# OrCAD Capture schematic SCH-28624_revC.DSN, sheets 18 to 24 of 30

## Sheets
18 16 XG-T PHY 1: size B
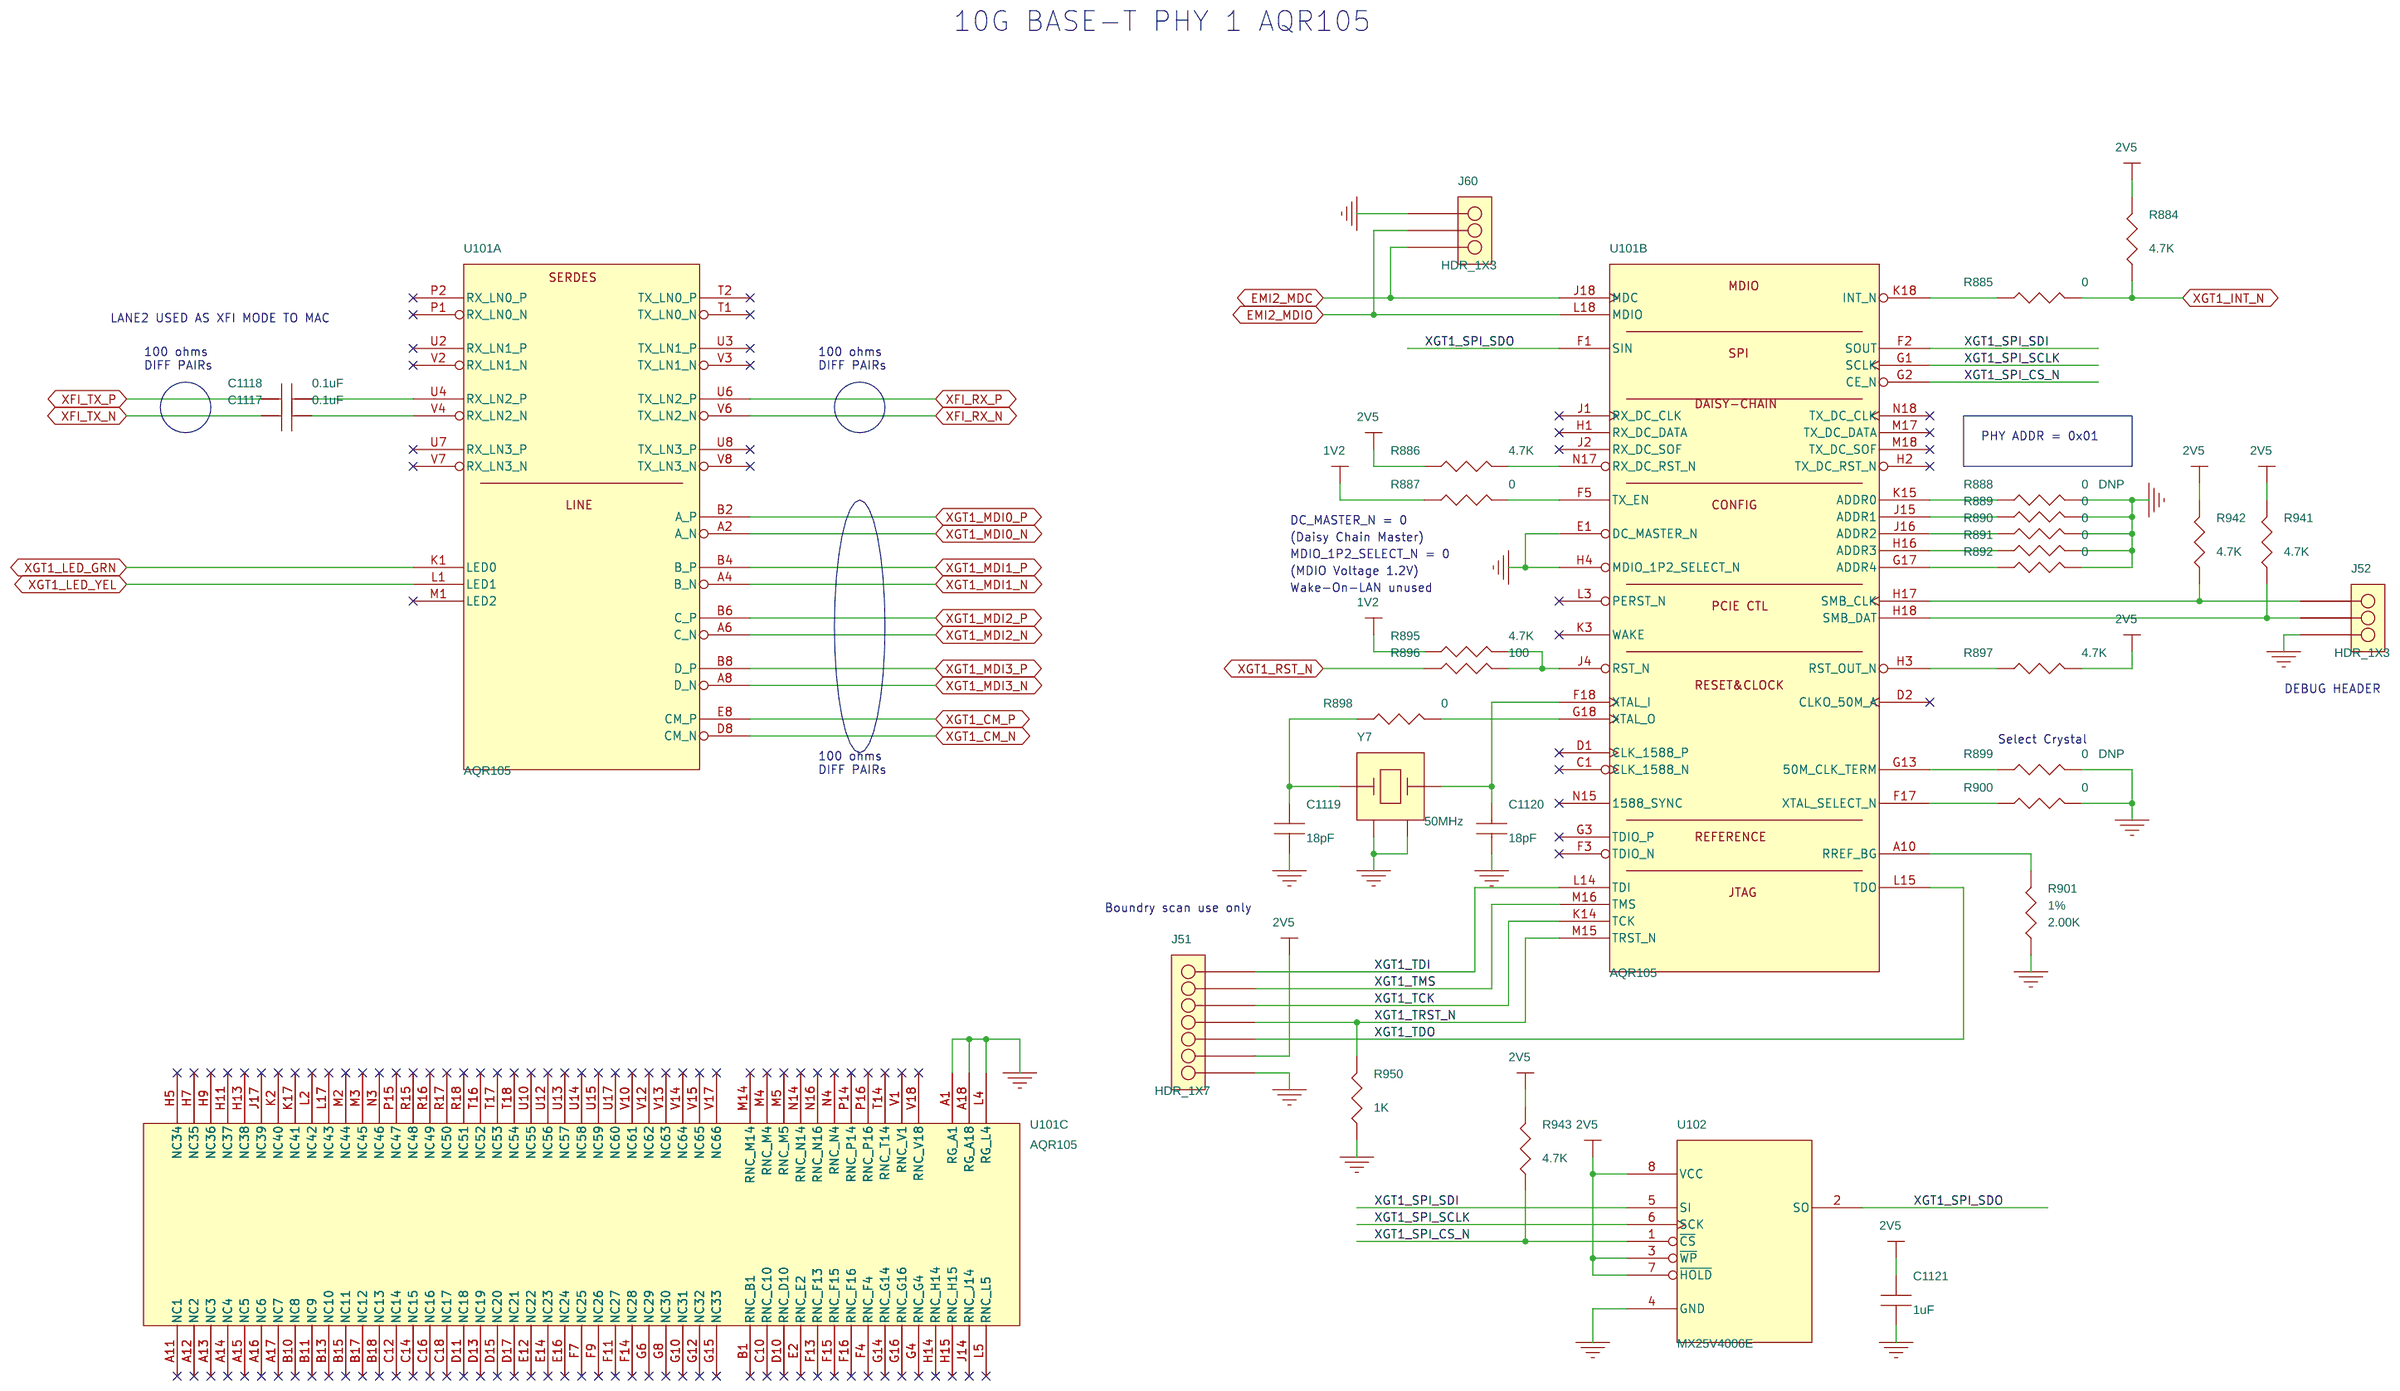
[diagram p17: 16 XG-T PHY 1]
19 17 XG-T PHY 1 Pwr: size B
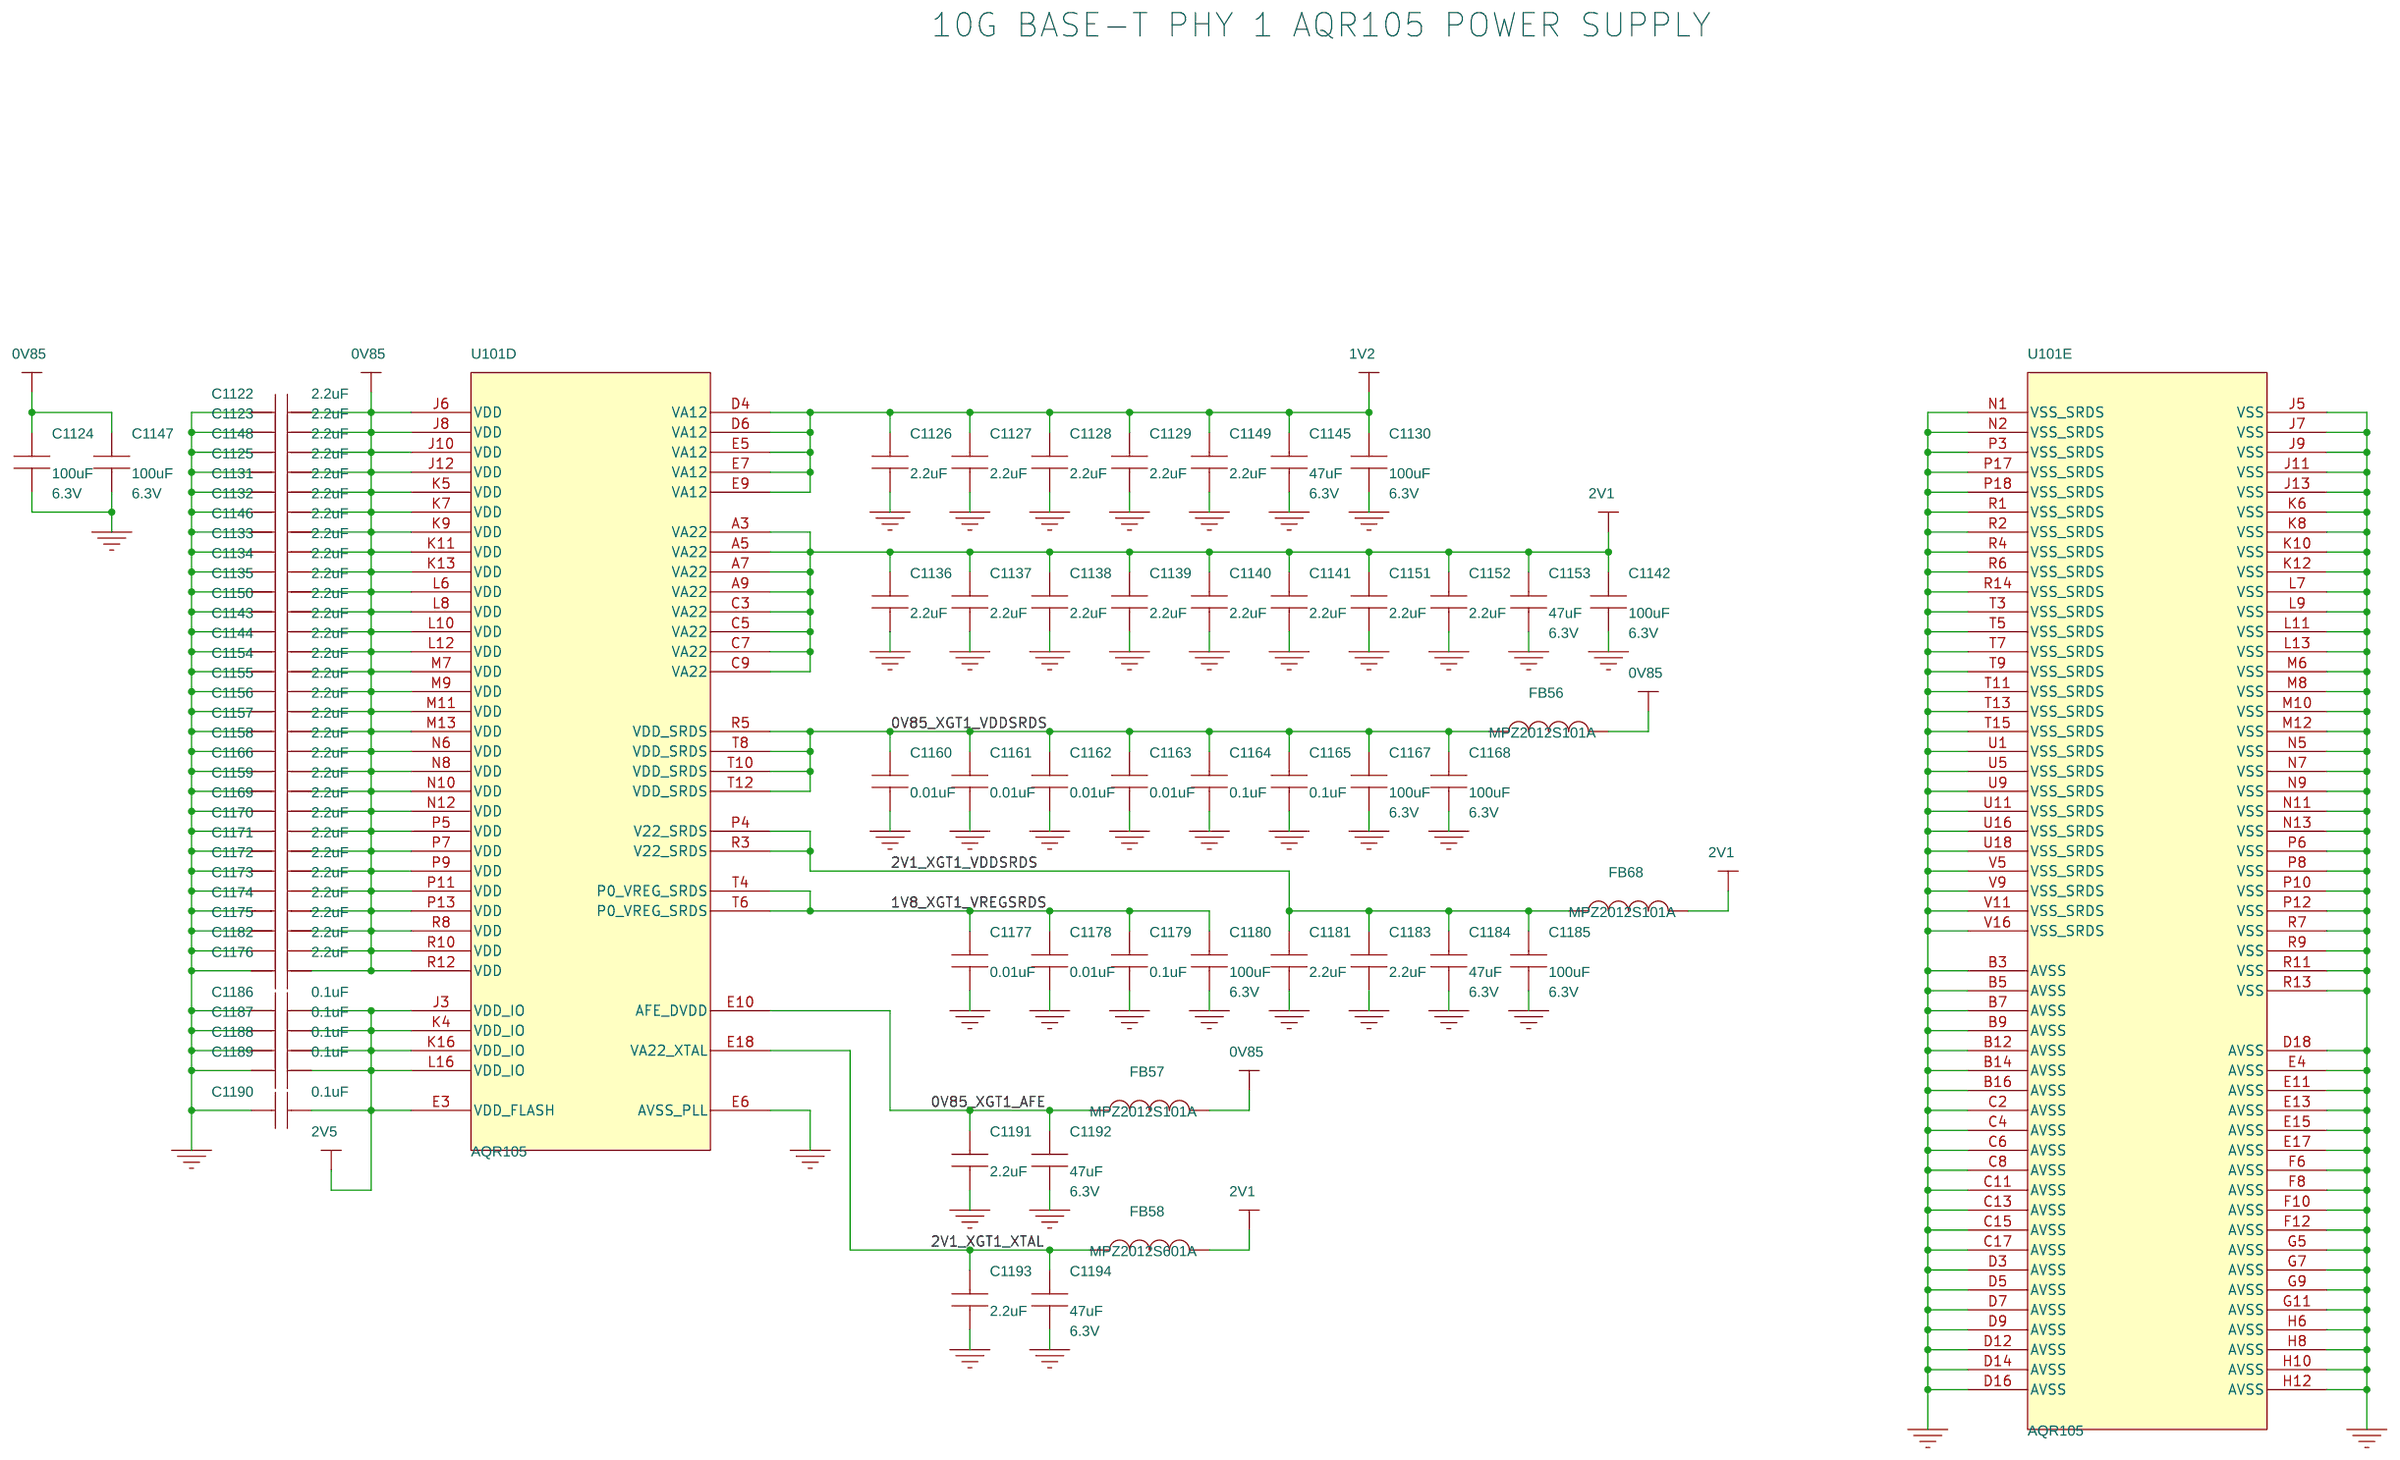
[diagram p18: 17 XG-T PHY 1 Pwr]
20 20 RJ46: size B
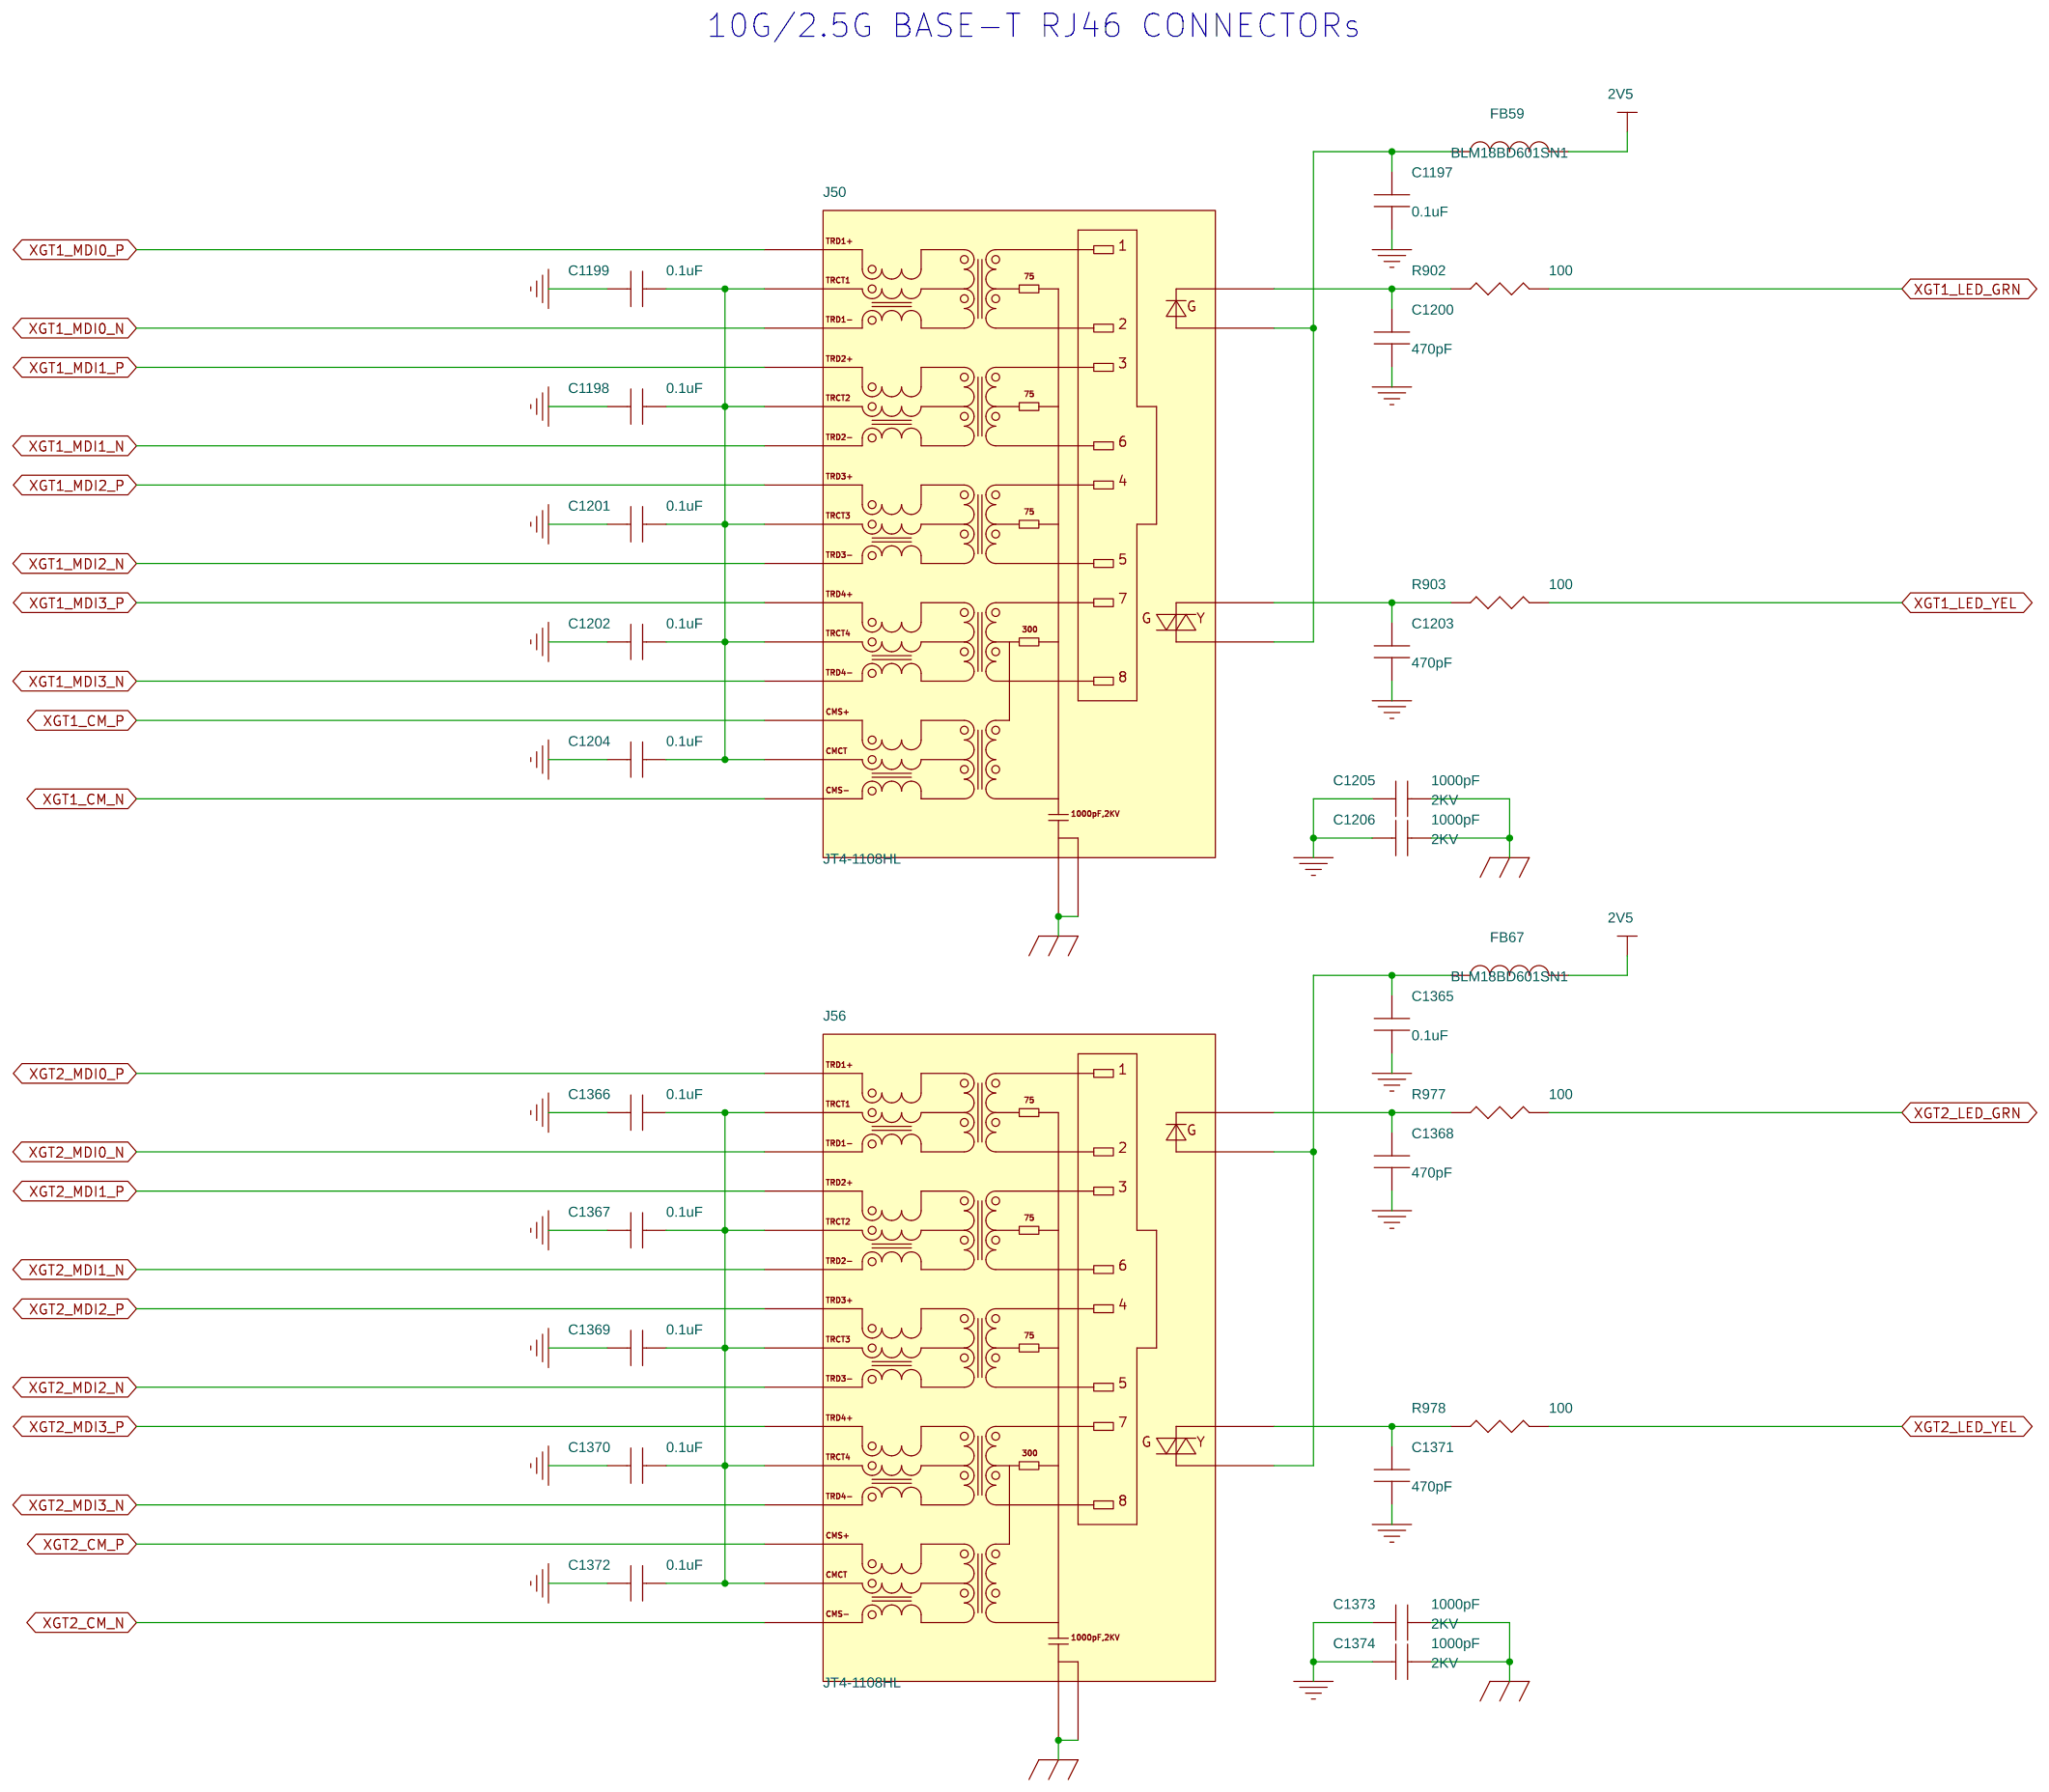
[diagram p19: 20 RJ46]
21 21 PCIe: size B
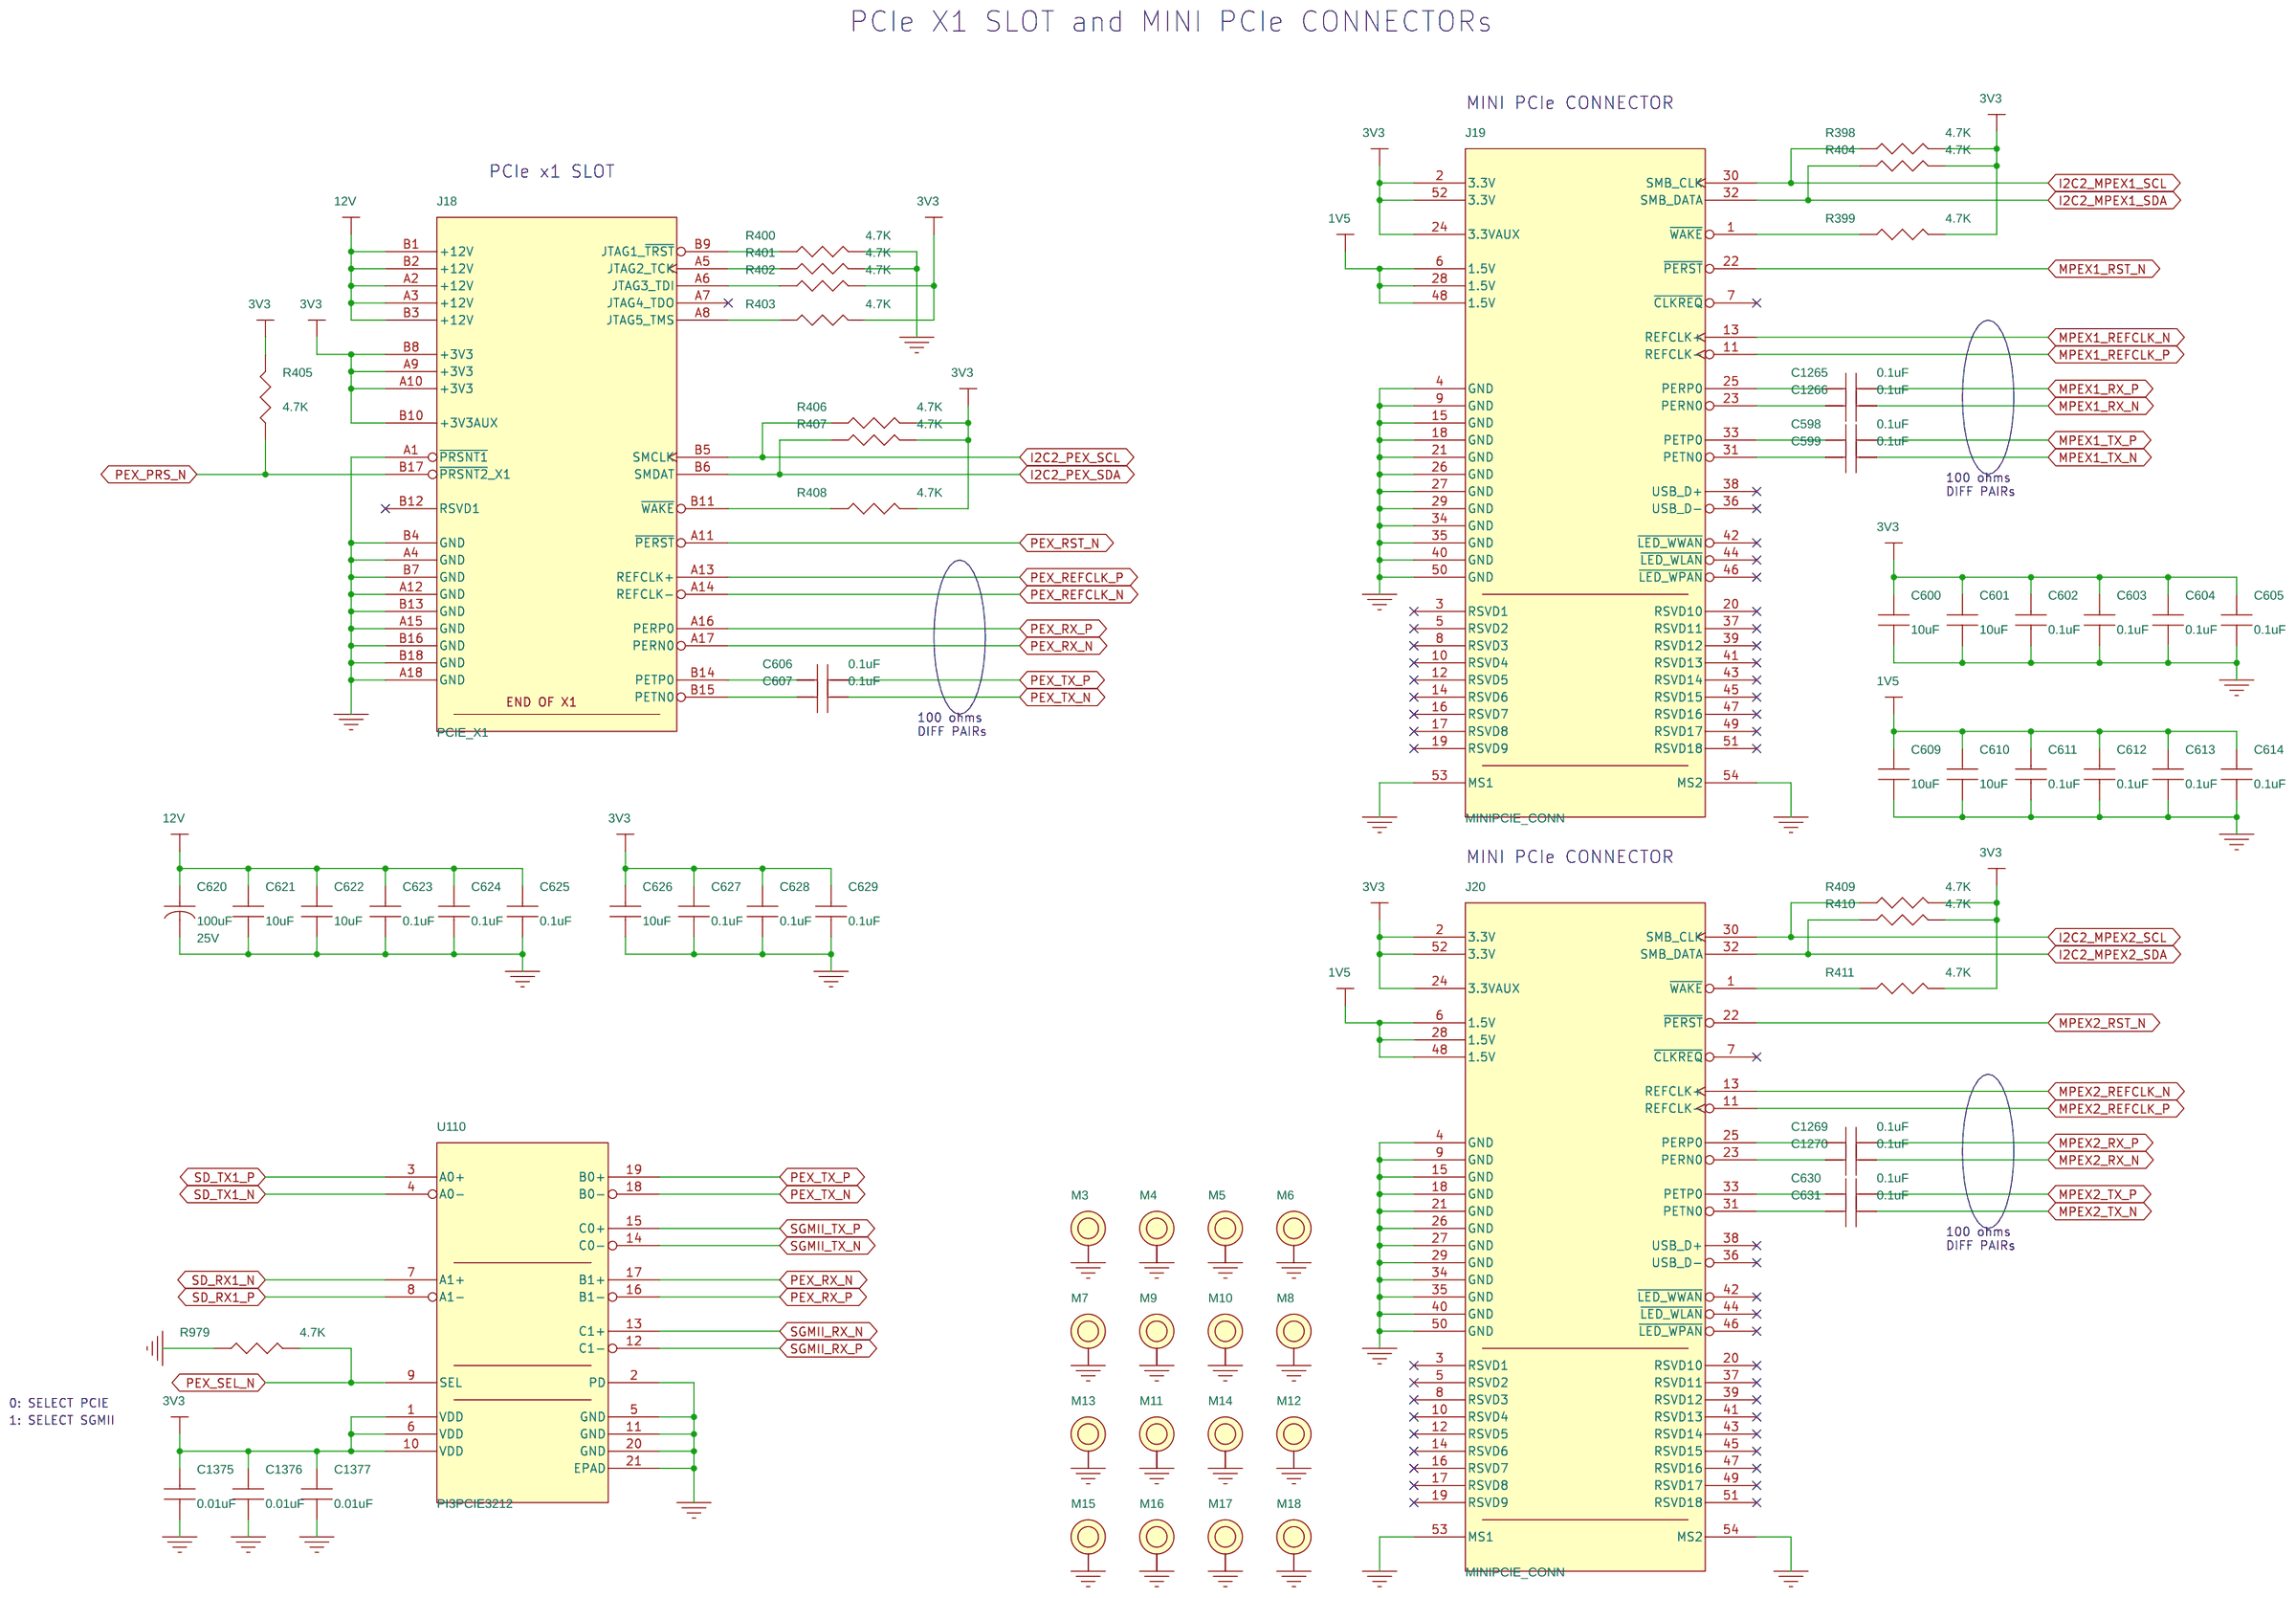
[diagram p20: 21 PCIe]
22 22 CPLD: size B
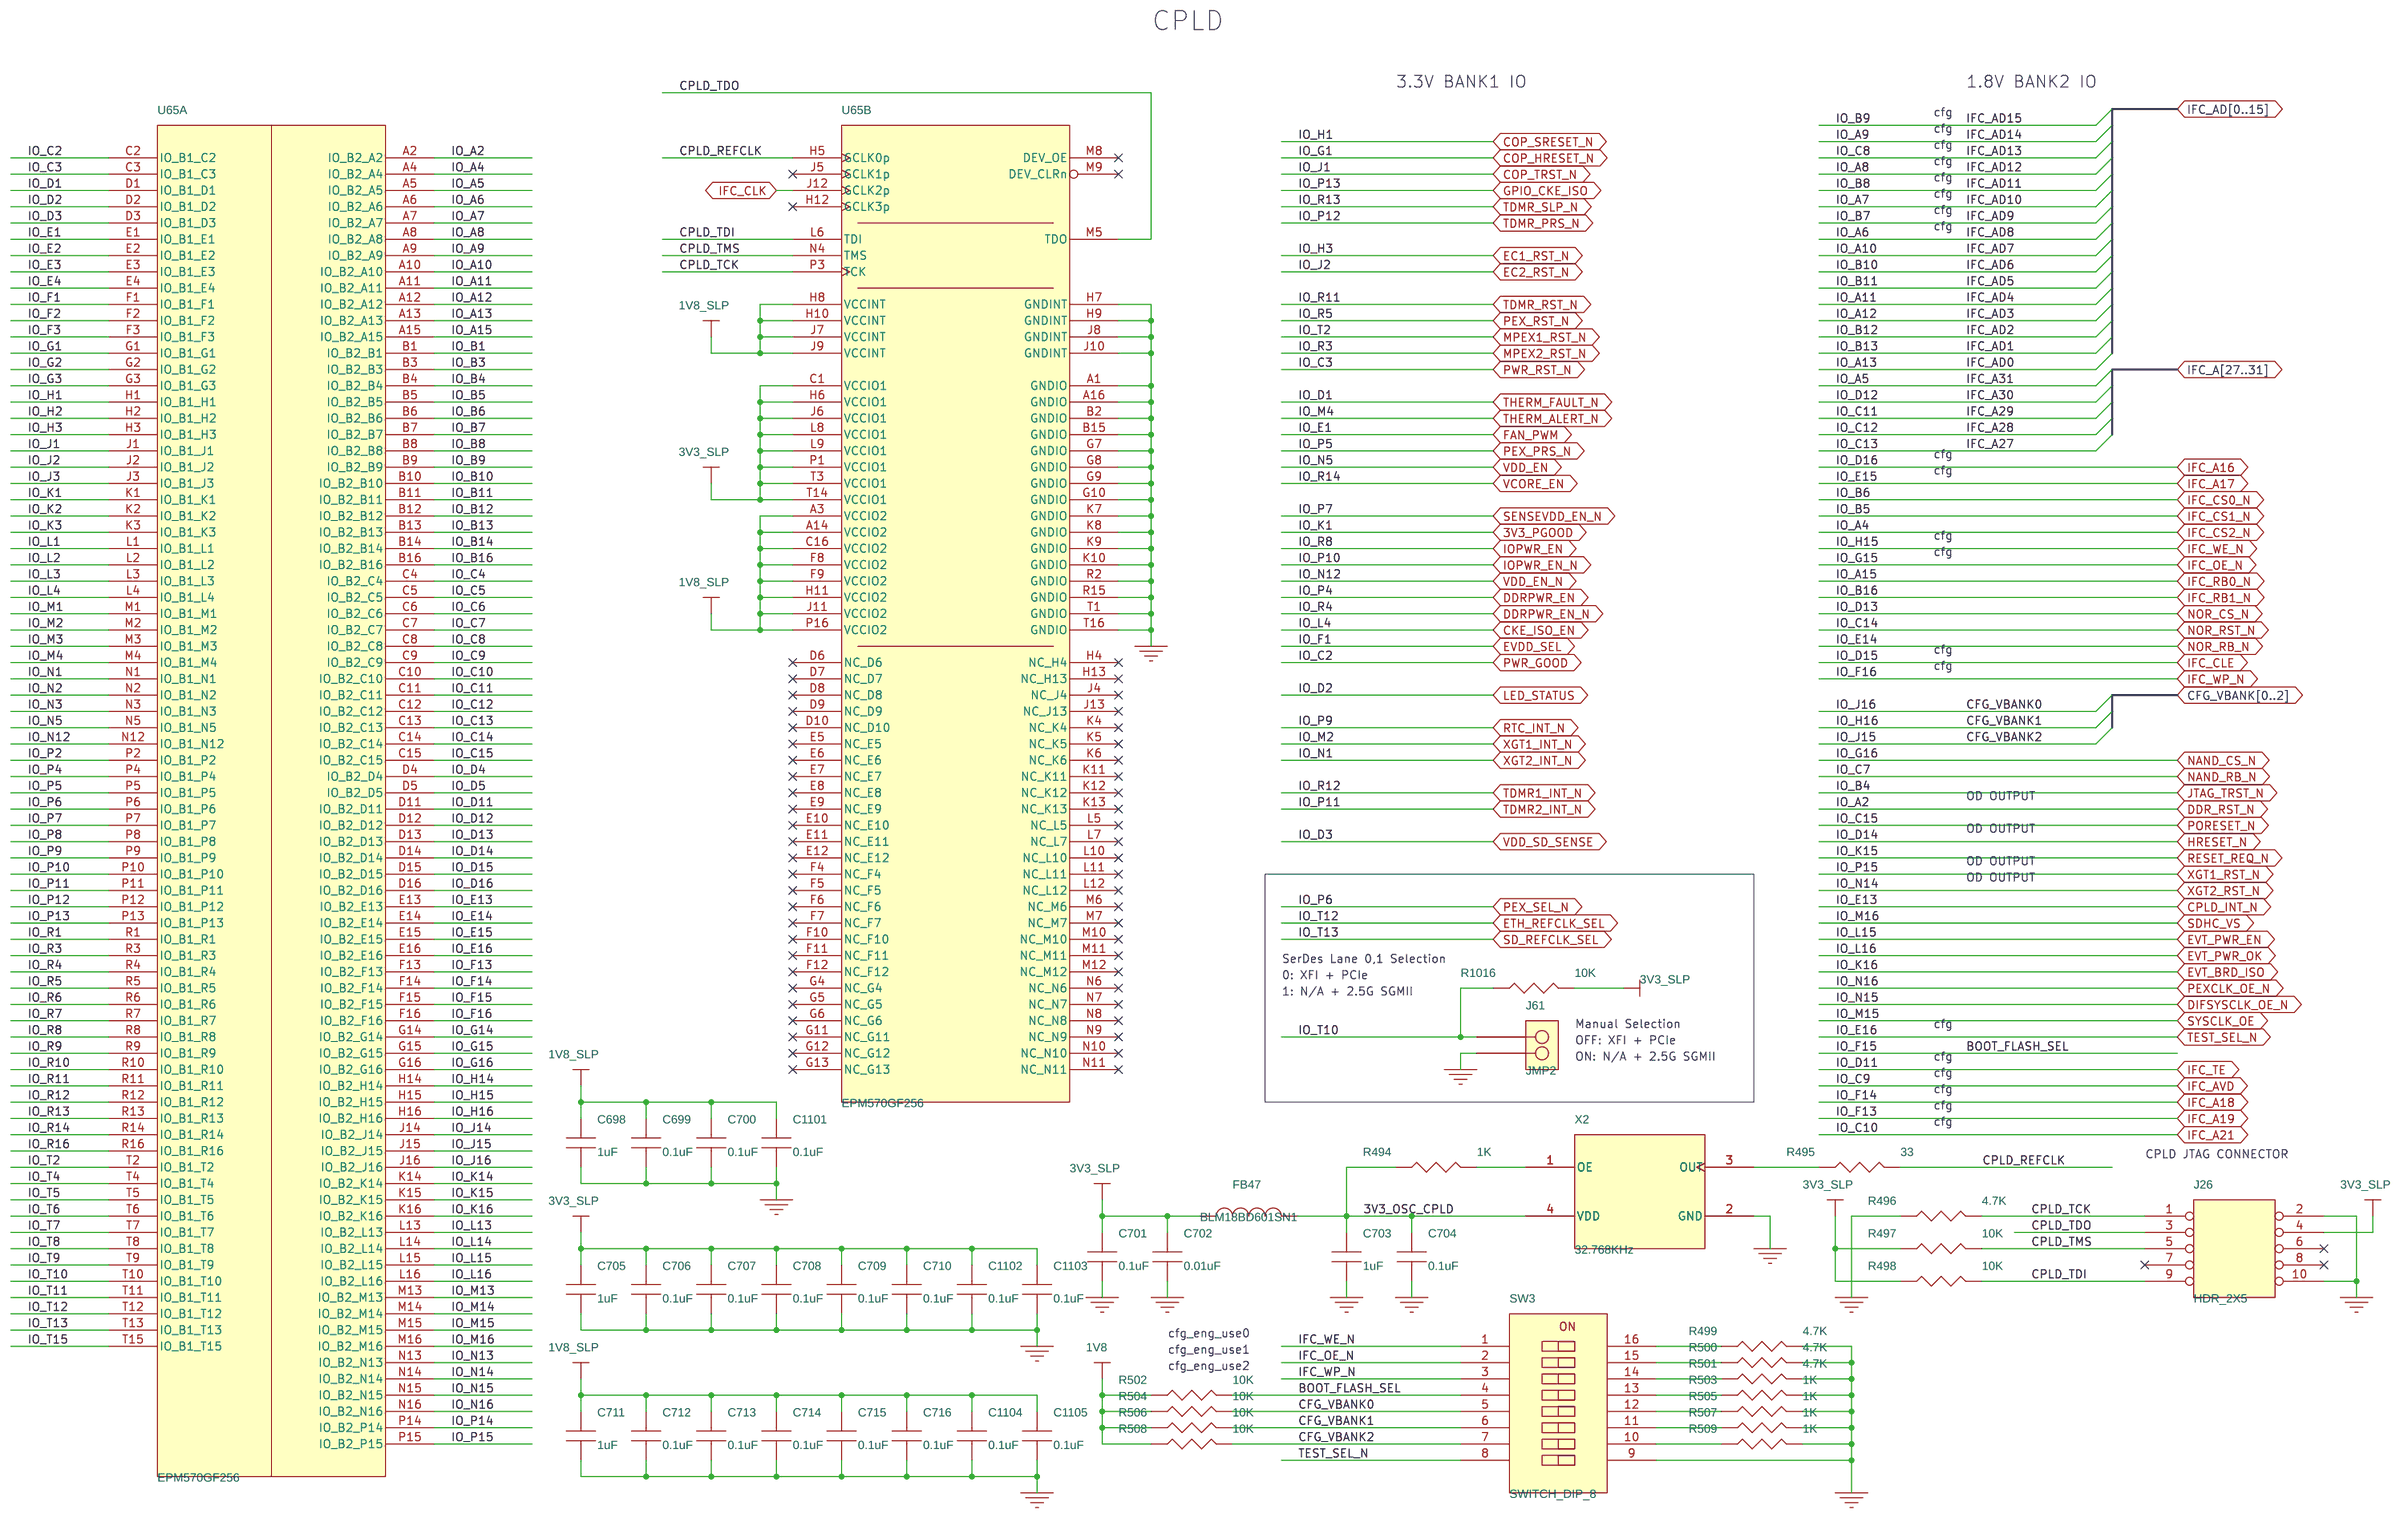
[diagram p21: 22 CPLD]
23 23 Clock 1: size B
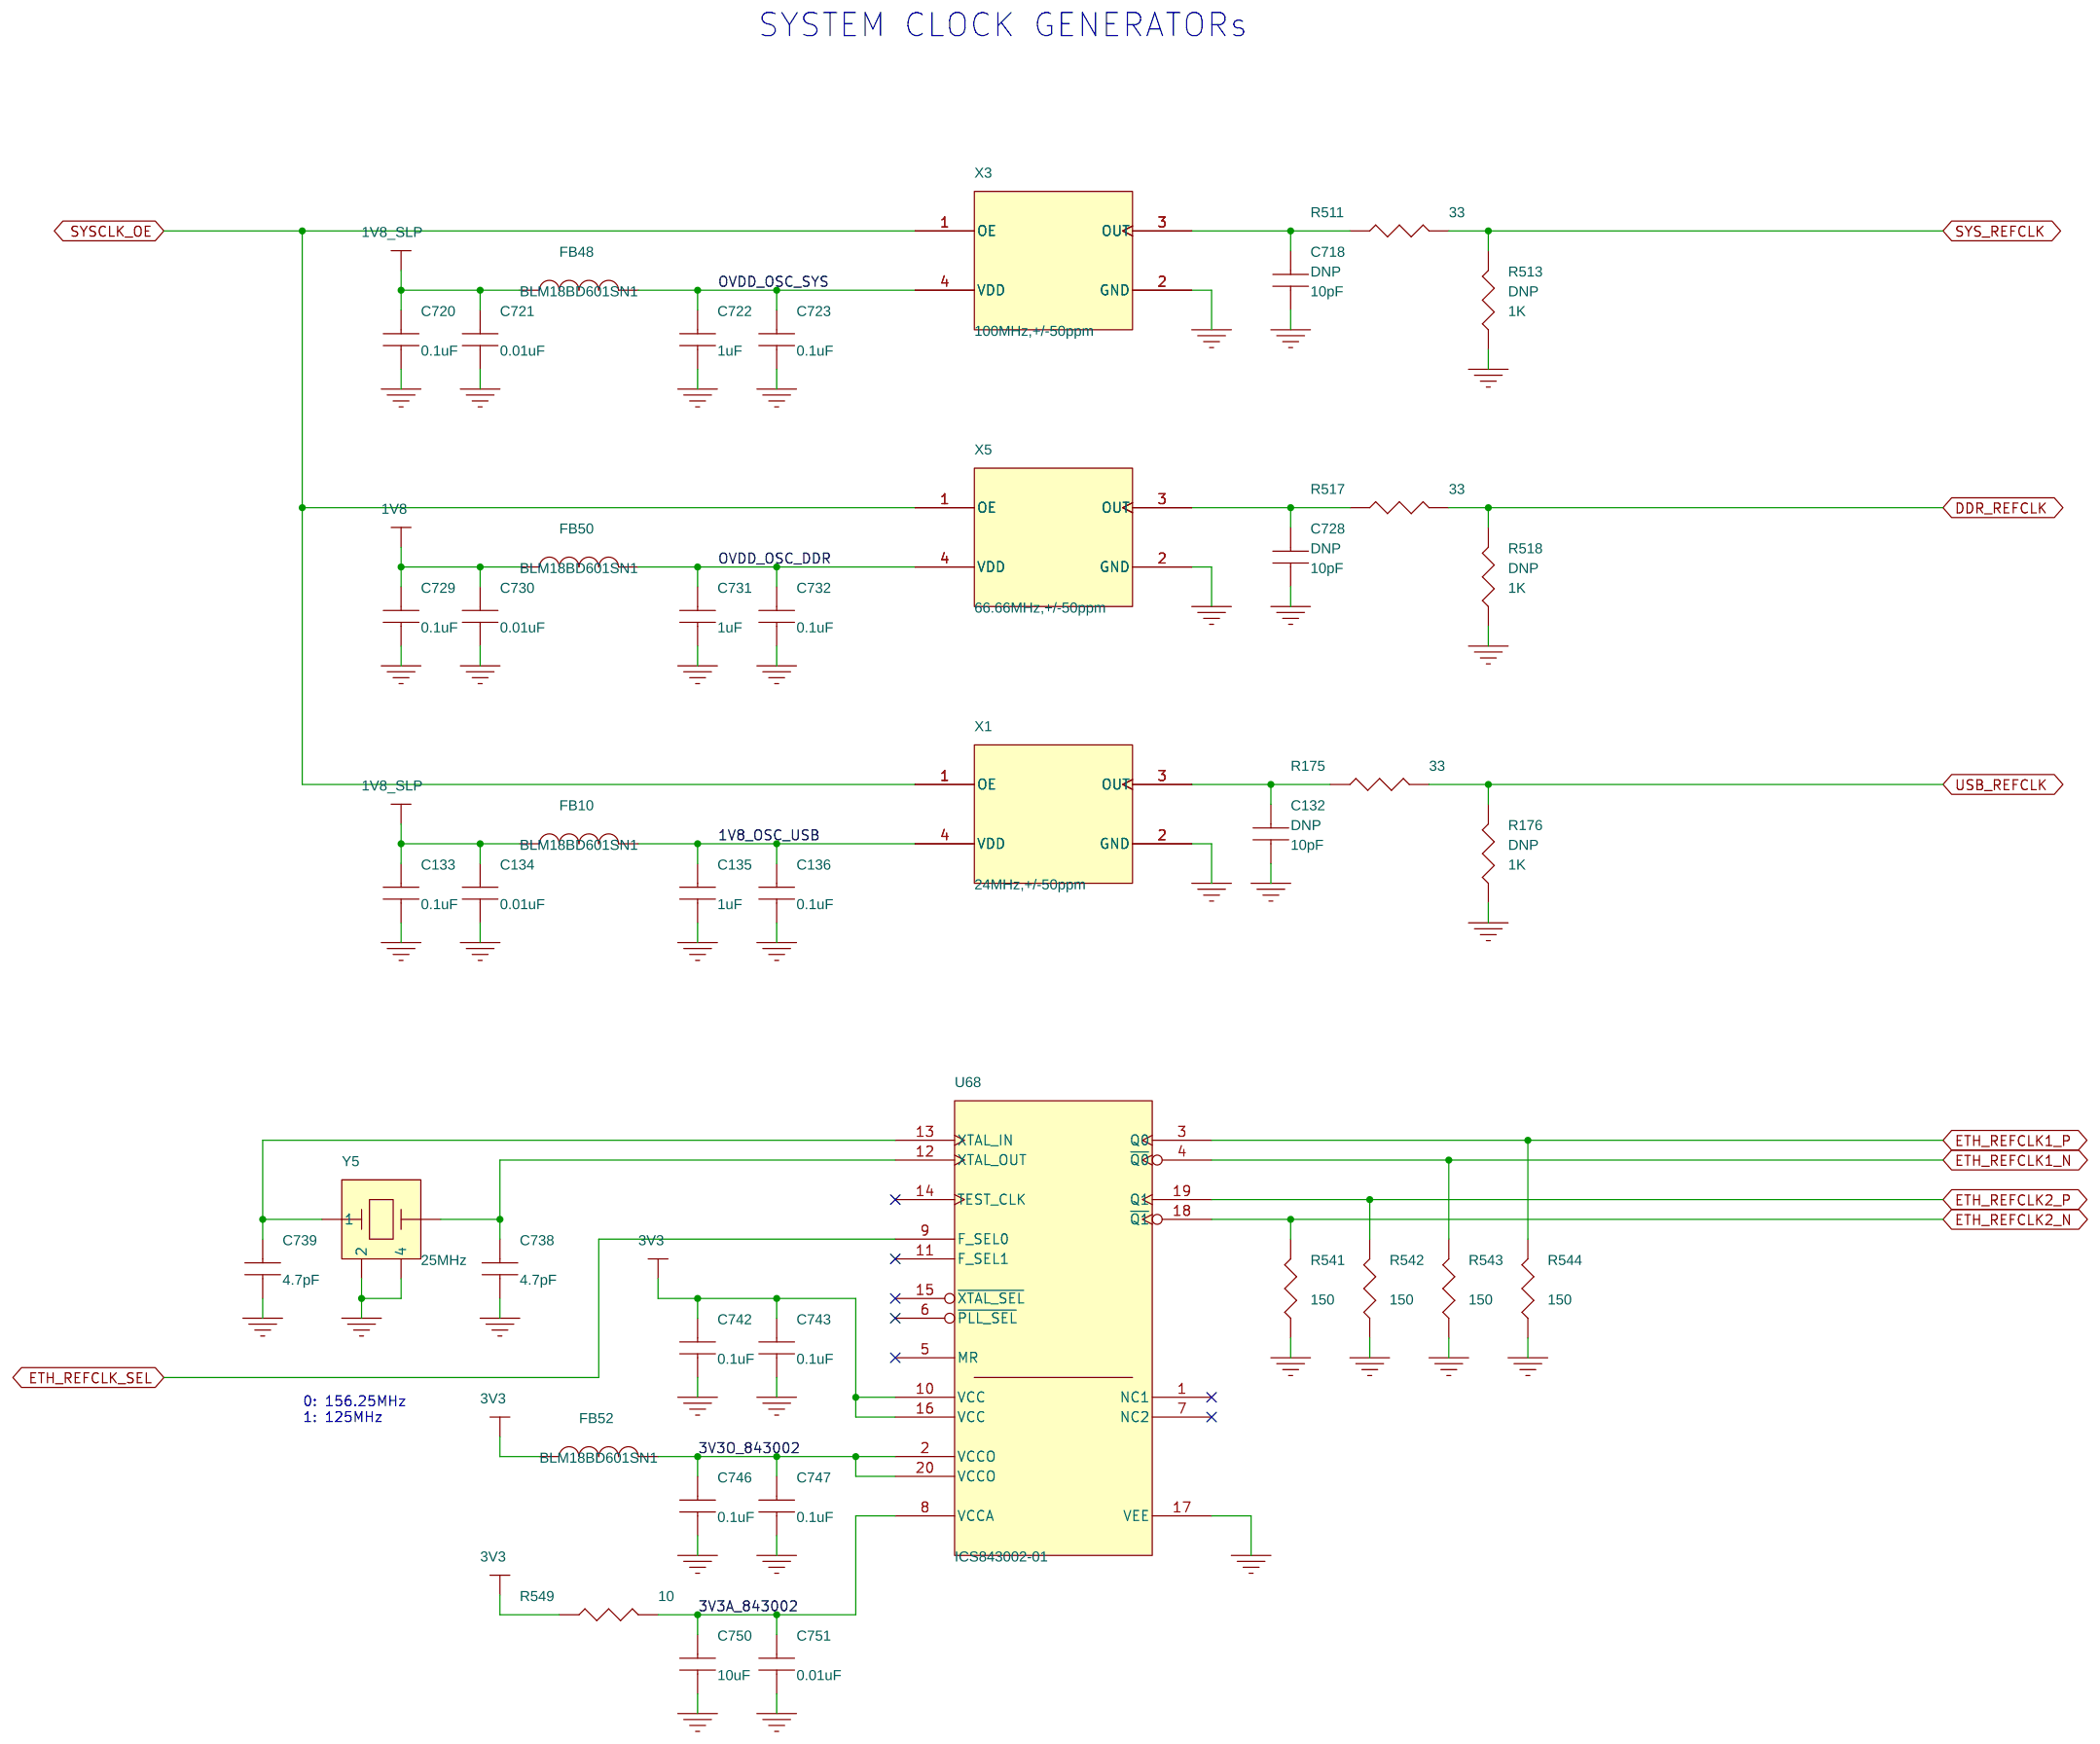
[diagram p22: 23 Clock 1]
24 24 Clock 2: size B
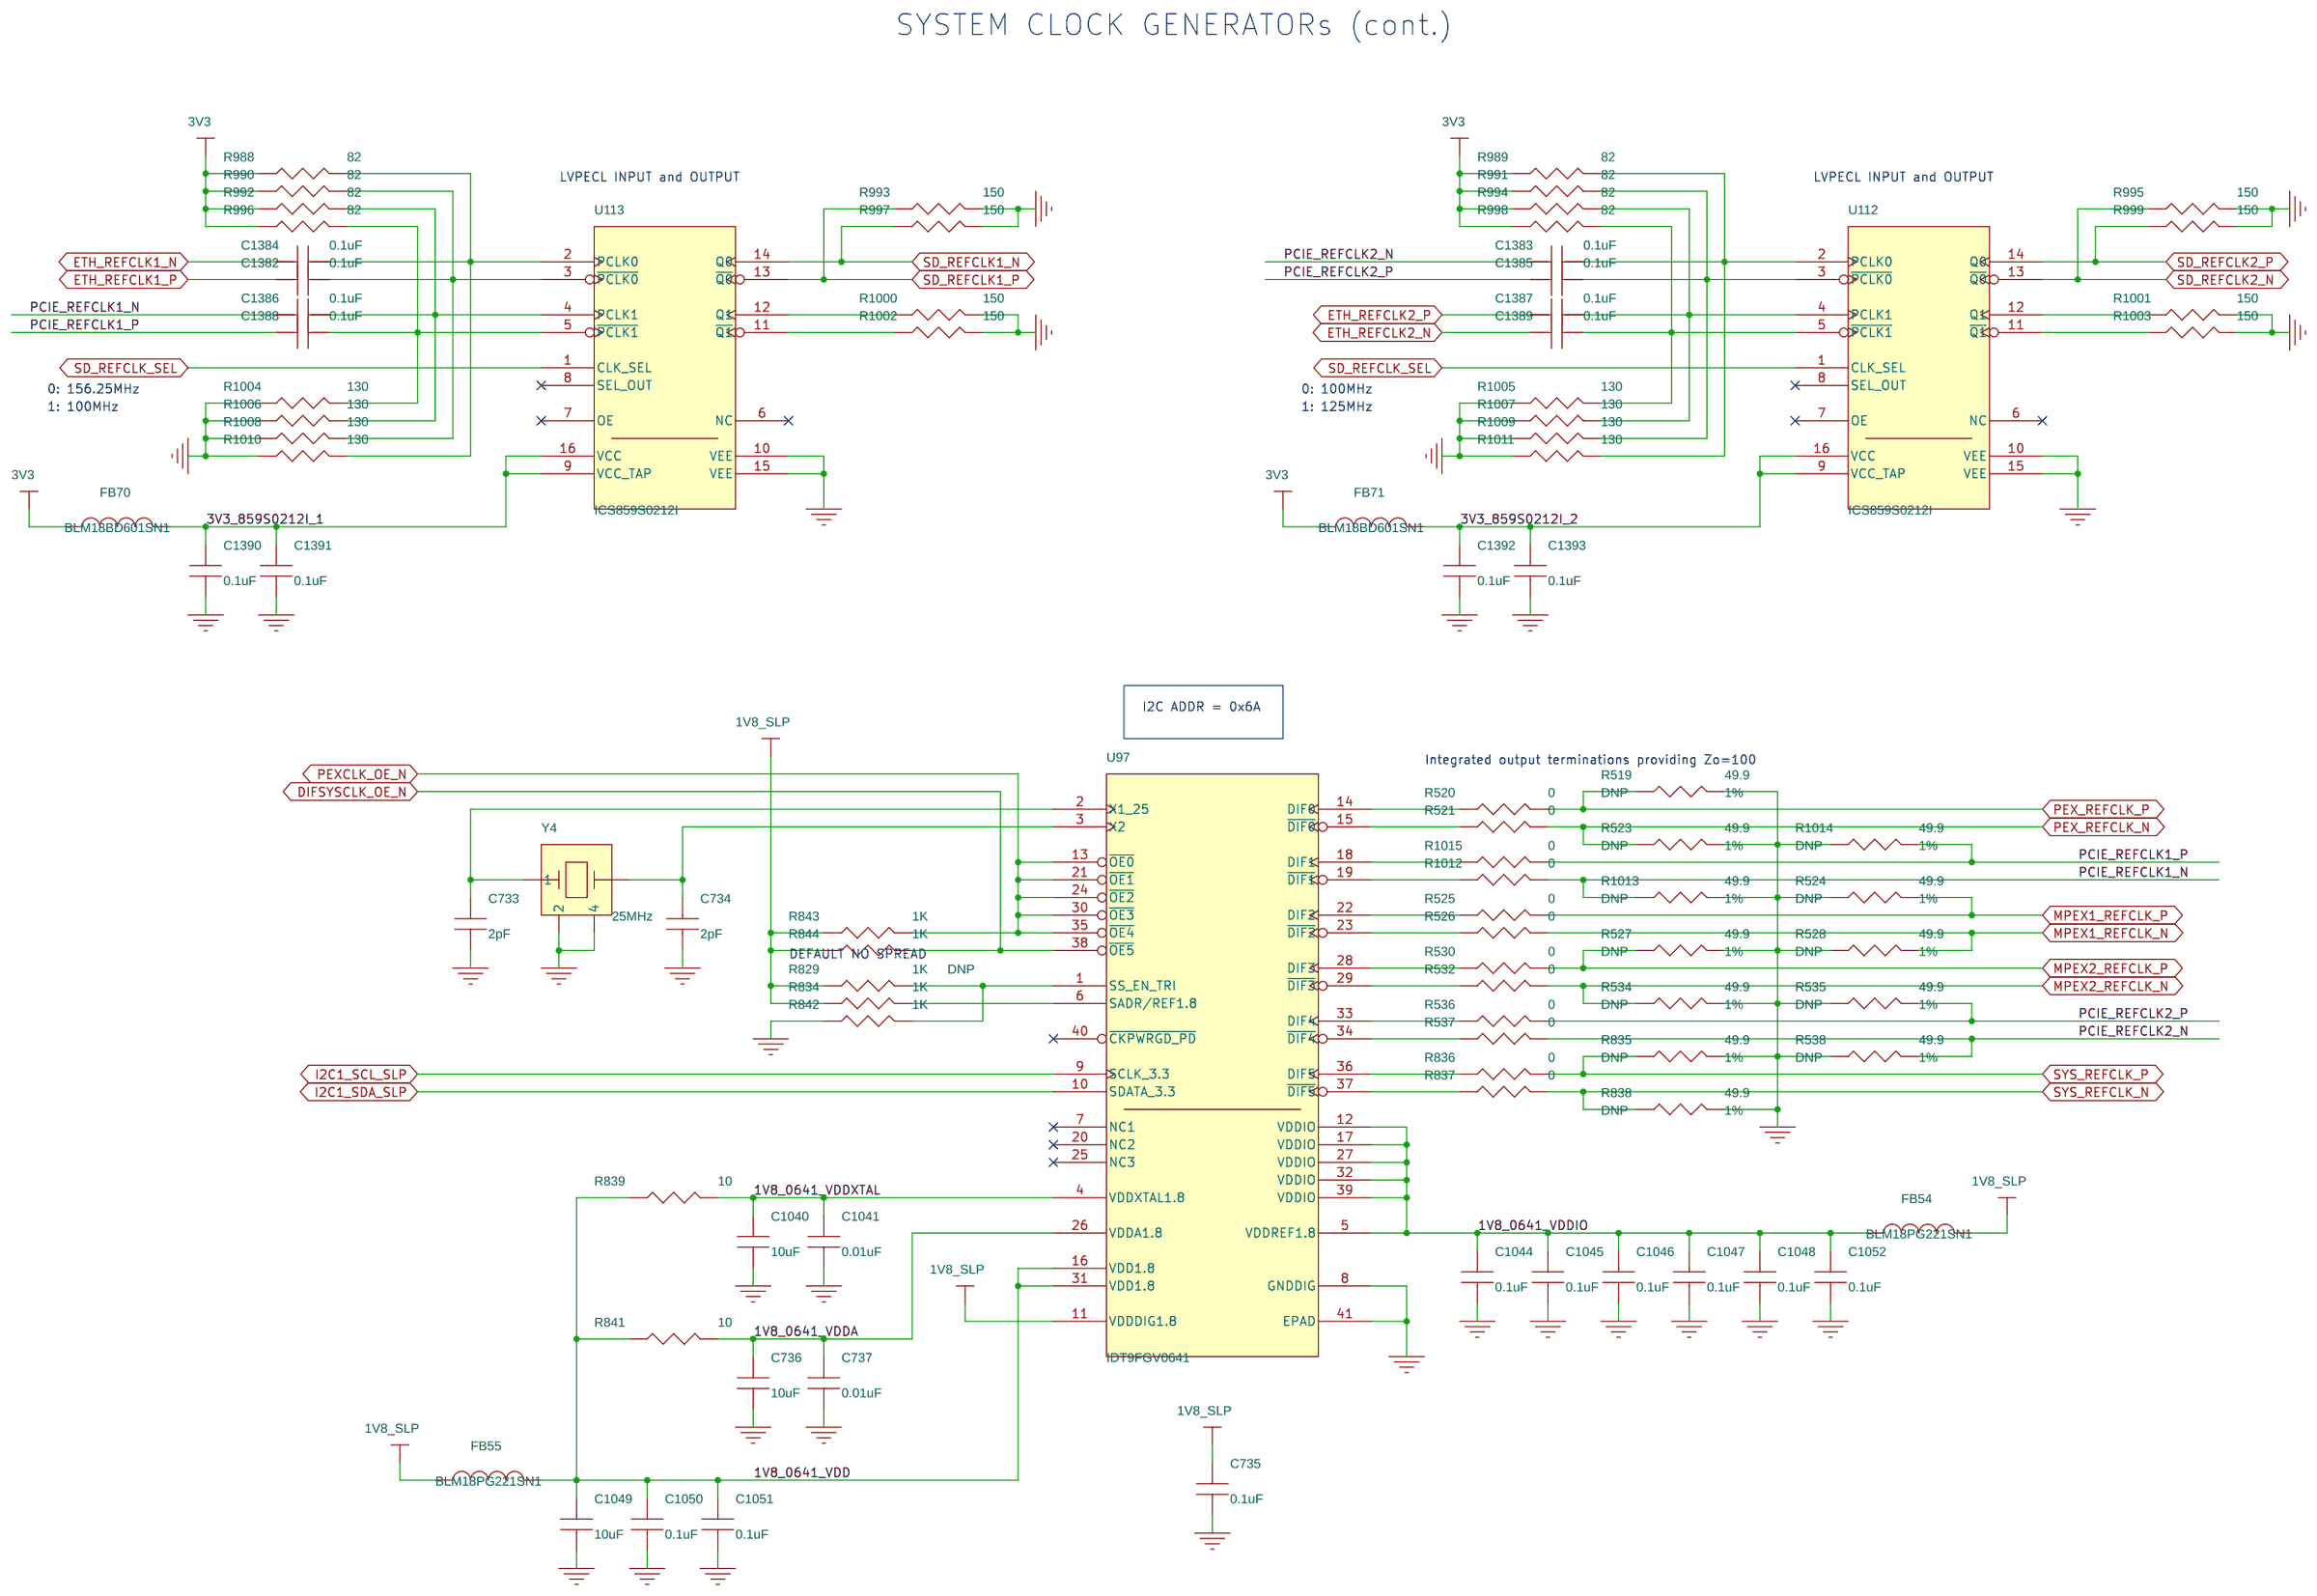
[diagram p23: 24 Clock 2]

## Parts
sheet 16 XG-T PHY 1
C1117  0.1uF  [0402]
C1118  0.1uF  [0402]
C1119  18pF  [0402]
C1120  18pF  [0402]
C1121  1uF  [0402]
J51  HDR_1X7  [hdr_p254_m_t_1x7]
J52  HDR_1X3  [hdr_p254_m_t_1x3]
J60  HDR_1X3  [hdr_p254_m_t_1x3]
R884  4.7K  [0402]
R885  0  [0402]
R886  4.7K  [0402]
R887  0  [0402]
R888  0  [0402]
R889  0  [0402]
R890  0  [0402]
R891  0  [0402]
R892  0  [0402]
R895  4.7K  [0402]
R896  100  [0402]
R897  4.7K  [0402]
R898  0  [0402]
R899  0  [0402]
R900  0  [0402]
R901  2.00K  [0402]
R941  4.7K  [0402]
R942  4.7K  [0402]
R943  4.7K  [0402]
R950  1K  [0402]
U101  AQR105  [bga_p100_324]  (sections A,B,C,D,E)
U102  MX25V4006E  [so_8]
Y7  50MHz  [cry_32x25_4]
sheet 17 XG-T PHY 1 Pwr
C1122  2.2uF  [0402]
C1123  2.2uF  [0402]
C1124  100uF  [1206]
C1125  2.2uF  [0402]
C1126  2.2uF  [0402]
C1127  2.2uF  [0402]
C1128  2.2uF  [0402]
C1129  2.2uF  [0402]
C1130  100uF  [1206]
C1131  2.2uF  [0402]
C1132  2.2uF  [0402]
C1133  2.2uF  [0402]
C1134  2.2uF  [0402]
C1135  2.2uF  [0402]
C1136  2.2uF  [0402]
C1137  2.2uF  [0402]
C1138  2.2uF  [0402]
C1139  2.2uF  [0402]
C1140  2.2uF  [0402]
C1141  2.2uF  [0402]
C1142  100uF  [1206]
C1143  2.2uF  [0402]
C1144  2.2uF  [0402]
C1145  47uF  [0805]
C1146  2.2uF  [0402]
C1147  100uF  [1206]
C1148  2.2uF  [0402]
C1149  2.2uF  [0402]
C1150  2.2uF  [0402]
C1151  2.2uF  [0402]
C1152  2.2uF  [0402]
C1153  47uF  [0805]
C1154  2.2uF  [0402]
C1155  2.2uF  [0402]
C1156  2.2uF  [0402]
C1157  2.2uF  [0402]
C1158  2.2uF  [0402]
C1159  2.2uF  [0402]
C1160  0.01uF  [0402]
C1161  0.01uF  [0402]
C1162  0.01uF  [0402]
C1163  0.01uF  [0402]
C1164  0.1uF  [0402]
C1165  0.1uF  [0402]
C1166  2.2uF  [0402]
C1167  100uF  [1206]
C1168  100uF  [1206]
C1169  2.2uF  [0402]
C1170  2.2uF  [0402]
C1171  2.2uF  [0402]
C1172  2.2uF  [0402]
C1173  2.2uF  [0402]
C1174  2.2uF  [0402]
C1175  2.2uF  [0402]
C1176  2.2uF  [0402]
C1177  0.01uF  [0402]
C1178  0.01uF  [0402]
C1179  0.1uF  [0402]
C1180  100uF  [1206]
C1181  2.2uF  [0402]
C1182  2.2uF  [0402]
C1183  2.2uF  [0402]
C1184  47uF  [0805]
C1185  100uF  [1206]
C1186  0.1uF  [0402]
C1187  0.1uF  [0402]
C1188  0.1uF  [0402]
C1189  0.1uF  [0402]
C1190  0.1uF  [0402]
C1191  2.2uF  [0402]
C1192  47uF  [0805]
C1193  2.2uF  [0402]
C1194  47uF  [0805]
FB56  MPZ2012S101A  [0805]
FB57  MPZ2012S101A  [0805]
FB58  MPZ2012S601A  [0805]
FB68  MPZ2012S101A  [0805]
sheet 20 RJ46
C1197  0.1uF  [0402]
C1198  0.1uF  [0402]
C1199  0.1uF  [0402]
C1200  470pF  [0402]
C1201  0.1uF  [0402]
C1202  0.1uF  [0402]
C1203  470pF  [0402]
C1204  0.1uF  [0402]
C1205  1000pF  [1206]
C1206  1000pF  [1206]
C1365  0.1uF  [0402]
C1366  0.1uF  [0402]
C1367  0.1uF  [0402]
C1368  470pF  [0402]
C1369  0.1uF  [0402]
C1370  0.1uF  [0402]
C1371  470pF  [0402]
C1372  0.1uF  [0402]
C1373  1000pF  [1206]
C1374  1000pF  [1206]
FB59  BLM18BD601SN1  [0603]
FB67  BLM18BD601SN1  [0603]
J50  JT4-1108HL  [con_rj45_xg_1x1_led]
J56  JT4-1108HL  [con_rj45_xg_1x1_led]
R902  100  [0402]
R903  100  [0402]
R977  100  [0402]
R978  100  [0402]
sheet 21 PCIe
C598  0.1uF  [0402]
C599  0.1uF  [0402]
C600  10uF  [0603]
C601  10uF  [0603]
C602  0.1uF  [0402]
C603  0.1uF  [0402]
C604  0.1uF  [0402]
C605  0.1uF  [0402]
C606  0.1uF  [0402]
C607  0.1uF  [0402]
C609  10uF  [0603]
C610  10uF  [0603]
C611  0.1uF  [0402]
C612  0.1uF  [0402]
C613  0.1uF  [0402]
C614  0.1uF  [0402]
C620  100uF  [cape_b6d3]
C621  10uF  [1206]
C622  10uF  [1206]
C623  0.1uF  [0603]
C624  0.1uF  [0603]
C625  0.1uF  [0603]
C626  10uF  [0603]
C627  0.1uF  [0402]
C628  0.1uF  [0402]
C629  0.1uF  [0402]
C630  0.1uF  [0402]
C631  0.1uF  [0402]
C1265  0.1uF  [0402]
C1266  0.1uF  [0402]
C1269  0.1uF  [0402]
C1270  0.1uF  [0402]
C1375  0.01uF  [0402]
C1376  0.01uF  [0402]
C1377  0.01uF  [0402]
J18  PCIE_X1  [con_pex1]
J19  MINIPCIE_CONN  [con_minipcie]
J20  MINIPCIE_CONN  [con_minipcie]
M3  MH  [mh_580s340p]
M4  MH  [mh_580s340p]
M5  MH  [mh_580s340p]
M6  MH  [mh_580s340p]
M7  MH  [mh_580s340p]
M8  MH  [mh_580s340p]
M9  MH  [mh_580s340p]
M10  MH  [mh_580s340p]
M11  MH  [mh_580s340p]
M12  MH  [mh_580s340p]
M13  MH  [mh_580s340p]
M14  MH  [mh_580s340p]
M15  MH  [mh_580s340p]
M16  MH  [mh_580s340p]
M17  MH  [mh_580s340p]
M18  MH  [mh_580s340p]
R398  4.7K  [0402]
R399  4.7K  [0402]
R400  4.7K  [0402]
R401  4.7K  [0402]
R402  4.7K  [0402]
R403  4.7K  [0402]
R404  4.7K  [0402]
R405  4.7K  [0402]
R406  4.7K  [0402]
R407  4.7K  [0402]
R408  4.7K  [0402]
R409  4.7K  [0402]
R410  4.7K  [0402]
R411  4.7K  [0402]
R979  4.7K  [0402]
U110  PI3PCIE3212  [qfn_p050_d040_b450x250_20_e3x1]
sheet 22 CPLD
C698  1uF  [0402o]
C699  0.1uF  [0402o]
C700  0.1uF  [0402o]
C701  0.1uF  [0402]
C702  0.01uF  [0402]
C703  1uF  [0402]
C704  0.1uF  [0402]
C705  1uF  [0402o]
C706  0.1uF  [0402o]
C707  0.1uF  [0402o]
C708  0.1uF  [0402o]
C709  0.1uF  [0402o]
C710  0.1uF  [0402o]
C711  1uF  [0402o]
C712  0.1uF  [0402o]
C713  0.1uF  [0402o]
C714  0.1uF  [0402o]
C715  0.1uF  [0402o]
C716  0.1uF  [0402o]
C1101  0.1uF  [0402o]
C1102  0.1uF  [0402o]
C1103  0.1uF  [0402o]
C1104  0.1uF  [0402o]
C1105  0.1uF  [0402o]
FB47  BLM18BD601SN1  [0603]
J26  HDR_2X5  [hdr_p254_m_t_2x5]
J61  JMP2  [jmp_p254_t_1x2]
R494  1K  [0402]
R495  33  [0402]
R496  4.7K  [0402]
R497  10K  [0402]
R498  10K  [0402]
R499  4.7K  [0402]
R500  4.7K  [0402]
R501  4.7K  [0402]
R502  10K  [0402]
R503  1K  [0402]
R504  10K  [0402]
R505  1K  [0402]
R506  10K  [0402]
R507  1K  [0402]
R508  10K  [0402]
R509  1K  [0402]
R1016  10K  [0402]
SW3  SWITCH_DIP_8  [con_switch_x8]
U65  EPM570GF256  [bga_p100_256]  (sections A,B)
X2  32.768KHz  [osc_32x25_4]
sheet 23 Clock 1
C132  10pF  [0402]
C133  0.1uF  [0402]
C134  0.01uF  [0402]
C135  1uF  [0402]
C136  0.1uF  [0402]
C718  10pF  [0402]
C720  0.1uF  [0402]
C721  0.01uF  [0402]
C722  1uF  [0402]
C723  0.1uF  [0402]
C728  10pF  [0402]
C729  0.1uF  [0402]
C730  0.01uF  [0402]
C731  1uF  [0402]
C732  0.1uF  [0402]
C738  4.7pF  [0402]
C739  4.7pF  [0402]
C742  0.1uF  [0402]
C743  0.1uF  [0402]
C746  0.1uF  [0402]
C747  0.1uF  [0402]
C750  10uF  [0603]
C751  0.01uF  [0402]
FB10  BLM18BD601SN1  [0603]
FB48  BLM18BD601SN1  [0603]
FB50  BLM18BD601SN1  [0603]
FB52  BLM18BD601SN1  [0603]
R175  33  [0402]
R176  1K  [0402]
R511  33  [0402]
R513  1K  [0402]
R517  33  [0402]
R518  1K  [0402]
R541  150  [0402]
R542  150  [0402]
R543  150  [0402]
R544  150  [0402]
R549  10  [0402]
U68  ICS843002-01  [tssop_20]
X1  24MHz,+/-50ppm  [osc_7x5_4]
X3  100MHz,+/-50ppm  [osc_7x5_4]
X5  66.66MHz,+/-50ppm  [osc_7x5_4]
Y5  25MHz  [cry_32x25_4]
sheet 24 Clock 2
C733  2pF  [0402]
C734  2pF  [0402]
C735  0.1uF  [0402]
C736  10uF  [0603]
C737  0.01uF  [0402]
C1040  10uF  [0603]
C1041  0.01uF  [0402]
C1044  0.1uF  [0402]
C1045  0.1uF  [0402]
C1046  0.1uF  [0402]
C1047  0.1uF  [0402]
C1048  0.1uF  [0402]
C1049  10uF  [0603]
C1050  0.1uF  [0402]
C1051  0.1uF  [0402]
C1052  0.1uF  [0402]
C1382  0.1uF  [0402]
C1383  0.1uF  [0402]
C1384  0.1uF  [0402]
C1385  0.1uF  [0402]
C1386  0.1uF  [0402]
C1387  0.1uF  [0402]
C1388  0.1uF  [0402]
C1389  0.1uF  [0402]
C1390  0.1uF  [0402]
C1391  0.1uF  [0402]
C1392  0.1uF  [0402]
C1393  0.1uF  [0402]
FB54  BLM18PG221SN1  [0603]
FB55  BLM18PG221SN1  [0603]
FB70  BLM18BD601SN1  [0603]
FB71  BLM18BD601SN1  [0603]
R519  49.9  [0402]
R520  0  [0402]
R521  0  [0402]
R523  49.9  [0402]
R524  49.9  [0402]
R525  0  [0402]
R526  0  [0402]
R527  49.9  [0402]
R528  49.9  [0402]
R530  0  [0402]
R532  0  [0402]
R534  49.9  [0402]
R535  49.9  [0402]
R536  0  [0402]
R537  0  [0402]
R538  49.9  [0402]
R829  1K  [0402]
R834  1K  [0402]
R835  49.9  [0402]
R836  0  [0402]
R837  0  [0402]
R838  49.9  [0402]
R839  10  [0402]
R841  10  [0402]
R842  1K  [0402]
R843  1K  [0402]
R844  1K  [0402]
R988  82  [0402]
R989  82  [0402]
R990  82  [0402]
R991  82  [0402]
R992  82  [0402]
R993  150  [0402]
R994  82  [0402]
R995  150  [0402]
R996  82  [0402]
R997  150  [0402]
R998  82  [0402]
R999  150  [0402]
R1000  150  [0402]
R1001  150  [0402]
R1002  150  [0402]
R1003  150  [0402]
R1004  130  [0402]
R1005  130  [0402]
R1006  130  [0402]
R1007  130  [0402]
R1008  130  [0402]
R1009  130  [0402]
R1010  130  [0402]
R1011  130  [0402]
R1012  0  [0402]
R1013  49.9  [0402]
R1014  49.9  [0402]
R1015  0  [0402]
U97  IDT9FGV0641  [qfn_p040_d040_b500_40_e370]
U112  ICS859S0212I  [tssop_16]
U113  ICS859S0212I  [tssop_16]
Y4  25MHz  [cry_32x25_4]

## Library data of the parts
C133 C136 C598 C599 C602-C607 C611-C614 C627-C631 C699-C701 C704 C706-C710 C712-C716 C720 C723 C729 C732 C735 C742 C743 C746 C747 C1044-C1048 C1050-C1052 C1101-C1105 C1117 C1118 C1164 C1165 C1179 C1186-C1190 C1197-C1199 C1201 C1202 C1204 C1265 C1266 C1269 C1270 C1365-C1367 C1369 C1370 C1372 C1382-C1393 = CAP: AGILE_PN: 150-75663; VOLTAGE: 16V
C1119 C1120 = CAP: AGILE_PN: 150-75658; VOLTAGE: 50V
C135 C698 C703 C705 C711 C722 C731 C1121 = CAP: AGILE_PN: 150-75421; VOLTAGE: 6.3V
J51 = CONN_1X7: AGILE_PN: 210-00129; MPN: TSW-107-07-F-S; TYPE: HDR; Vendor: Samtec
J52 J60 = CONN_1X3: AGILE_PN: 210-75442; MPN: TSW-103-07-F-S; TYPE: HDR; Vendor: Samtec
R398-R411 R496 R499-R501 R884 R886 R895 R897 R941-R943 R979 = RES: AGILE_PN: 470-75626; TOL: 5%
R520 R521 R525 R526 R530 R532 R536 R537 R836 R837 R885 R887 R889-R892 R898 R900 R1012 R1015 = RES: AGILE_PN: 470-75394; TOL: 5%
R176 R513 R518 R829 R888 R899 = RES: BOM_IGNORE: DNP; TOL: 5%
R896 R902 R903 R977 R978 = RES: AGILE_PN: 470-30454; TOL: 5%
R901 = RES: AGILE_PN: 470-75356; TOL: 1%
R494 R503 R505 R507 R509 R834 R842-R844 R950 = RES: AGILE_PN: 470-75555; TOL: 5%
U101 = AQ2104: AGILE_PN: 312-81040; ID: 1; MPN: AQR105-B0-EG-Y; TYPE: IC; Vendor: AQUANTIA
U102 = FLASH-SERIAL-SO8: AGILE_PN: 342-00610; MPN: MX25V4006EM1I-13G; TYPE: IC; Vendor: MXIC
Y7 = CRYSTAL_4PIN_v2: AGILE_PN: 230-00038; MPN: 3.2x2.5mm,4pin,CL=12pF,+/-20ppm; TYPE: XTAL
C1122 C1123 C1125 C1126 C1129 C1131 C1133-C1138 C1140 C1141 C1143 C1144 C1146 C1148-C1152 C1154-C1158 C1166 C1169-C1171 C1173 C1175 C1176 C1181-C1183 C1191 C1193 = CAP: AGILE_PN: 150-76792; VOLTAGE: 4V
C1124 C1130 C1142 C1147 C1167 C1168 C1180 C1185 = CAP: AGILE_PN: 150-77574; VOLTAGE: 6.3V
C1127 C1128 C1132 C1139 C1159 C1172 C1174 = CAP: AGILE_PN: 150-00094; VOLTAGE: 4V
C1145 C1153 C1184 C1192 C1194 = CAP: AGILE_PN: 150-79458; VOLTAGE: 6.3V
C134 C702 C721 C730 C737 C751 C1041 C1160-C1163 C1177 C1178 C1375-C1377 = CAP: AGILE_PN: 150-75183; VOLTAGE: 25V
FB56 FB57 FB68 = BEAD: AGILE_PN: 180-00041; Vendor: TDK
FB58 = BEAD: AGILE_PN: 180-00042; Vendor: TDK
C1200 C1203 C1368 C1371 = CAP: AGILE_PN: 150-75452; VOLTAGE: 50V
C1205 C1206 C1373 C1374 = CAP: AGILE_PN: 150-00046; VOLTAGE: 2KV
FB10 FB47 FB48 FB50 FB52 FB59 FB67 FB70 FB71 = BEAD: AGILE_PN: 180-75046; Vendor: Murata
J50 J56 = RJ45_XG_LED: AGILE_PN: 210-00066; TYPE: CON; Vendor: Pulse
C600 C601 C609 C610 C626 C736 C750 C1040 C1049 = CAP: AGILE_PN: 150-78675; VOLTAGE: 6.3V
C620 = CAP_E: AGILE_PN: 150-78769; TYPE: CAP; VOLTAGE: 25V
C621 C622 = CAP: AGILE_PN: 150-77350; VOLTAGE: 25V
C623-C625 = CAP: AGILE_PN: 150-75016; VOLTAGE: 25V
J18 = PCIE_X1: AGILE_PN: 210-78899; MPN: 87715-9001; TYPE: CON; Vendor: MOLEX
J19 J20 = MINIPCIE_CONN: AGILE_PN: 211-78066; MPN: 0717A01A68C; TYPE: CON; Vendor: CONCRAFT
M3-M18 = MH: MPN: 071CAAAZ68B; TYPE: CON; Vendor: CONCRAFT
U110 = PI3PCIE3212: AGILE_PN: 312-00101; MPN: PI3PCIE3212ZBE; TYPE: IC; Vendor: PERICOM
J26 = CONN_2X5: AGILE_PN: 210-30026; MPN: TSW-105-07-F-D; TYPE: HDR; Vendor: Samtec
J61 = CONN_1X2: AGILE_PN: 210-80733; MPN: TSW-102-07-F-S; TYPE: HDR; Vendor: Samtec
R175 R495 R511 R517 = RES: AGILE_PN: 470-75790; TOL: 5%
R497 R498 R502 R504 R506 R508 R1016 = RES: AGILE_PN: 470-75557; TOL: 5%
SW3 = SWITCH_DIP_8: AGILE_PN: 510-77751; MPN: DHNF-08F-V; TYPE: CON; Vendor: DIPTRONICS
U65 = EPM570F256: AGILE_PN: 313-75309; MPN: EPM570GF256C5N; TYPE: IC; Vendor: Altera
X2 = OSC: AGILE_PN: 230-77733; MPN: KK3270021; Vendor: PERICOM
C132 C718 C728 = CAP: BOM_IGNORE: DNP; VOLTAGE: 50V
C738 C739 = CAP: AGILE_PN: 150-75273; VOLTAGE: 50V
R541-R544 R993 R995 R997 R999-R1003 = RES: AGILE_PN: 470-30339; TOL: 5%
R549 R839 R841 = RES: AGILE_PN: 470-75589; TOL: 5%
U68 = ICS843002-01: AGILE_PN: 312-00097; MPN: 843002AG-01LF; TYPE: IC; Vendor: IDT
X1 = OSC: AGILE_PN: 230-00029; MPN: 5x7mm,1.8V,+/-50ppm
X3 = OSC: AGILE_PN: 230-00034; MPN: 5x7mm,1.8V,+/-50ppm
X5 = OSC: AGILE_PN: 230-00030; MPN: 5x7mm,1.8V,+/-50ppm
Y4 Y5 = CRYSTAL_4PIN: AGILE_PN: 230-77947; MPN: 3.2x2.5mm,4pin,CL=18pF,+/-20ppm; TYPE: XTAL
C733 C734 = CAP: AGILE_PN: 150-00078; VOLTAGE: 50V
FB54 FB55 = BEAD: AGILE_PN: 180-77775; Vendor: Murata
R519 R523 R524 R527 R528 R534 R535 R538 R835 R838 R1013 R1014 = RES: BOM_IGNORE: DNP; TOL: 1%
R988-R992 R994 R996 R998 = RES: AGILE_PN: 470-00150; TOL: 5%
R1004-R1011 = RES: AGILE_PN: 470-76421; TOL: 5%
U97 = IDT9FGV0641: AGILE_PN: 312-81108; MPN: 9FGV0641AKLF; TYPE: IC; Vendor: IDT
U112 U113 = ICS859S0212I: AGILE_PN: 312-00096; MPN: 859S0212BGILF; TYPE: IC; Vendor: IDT

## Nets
0V85: C1122.2 C1123.2 C1124.1 C1125.2 C1131.2 C1132.2 C1133.2 C1134.2 C1135.2 C1143.2 C1144.2 C1146.2 C1147.1 C1148.2 C1150.2 C1154.2 C1155.2 C1156.2 C1157.2 C1158.2 C1159.2 C1166.2 C1169.2 C1170.2 C1171.2 C1172.2 C1173.2 C1174.2 C1175.2 C1176.2 C1182.2 FB56.2 FB57.2 U101.J6(VDD) U101.J8(VDD) U101.J10(VDD) U101.J12(VDD) U101.K5(VDD) U101.K7(VDD) U101.K9(VDD) U101.K11(VDD) U101.K13(VDD) U101.L6(VDD) U101.L8(VDD) U101.L10(VDD) U101.L12(VDD) U101.M7(VDD) U101.M9(VDD) U101.M11(VDD) U101.M13(VDD) U101.N6(VDD) U101.N8(VDD) U101.N10(VDD) U101.N12(VDD) U101.P5(VDD) U101.P7(VDD) U101.P9(VDD) U101.P11(VDD) U101.P13(VDD) U101.R8(VDD) U101.R10(VDD) U101.R12(VDD) ; also on sheet 1 26
0V85_XGT1_AFE: C1191.1 C1192.1 FB57.1 U101.E10(AFE_DVDD)
0V85_XGT1_VDDSRDS: C1160.1 C1161.1 C1162.1 C1163.1 C1164.1 C1165.1 C1167.1 C1168.1 FB56.1 U101.R5(VDD_SRDS) U101.T8(VDD_SRDS) U101.T10(VDD_SRDS) U101.T12(VDD_SRDS)
1V2: C1126.1 C1127.1 C1128.1 C1129.1 C1130.1 C1145.1 C1149.1 R887.1 R895.1 U101.D4(VA12) U101.D6(VA12) U101.E5(VA12) U101.E7(VA12) U101.E9(VA12) ; also on sheet 1 2 10 13 25
1V5: C609.1 C610.1 C611.1 C612.1 C613.1 C614.1 J19.6(1.5V) J19.28(1.5V) J19.48(1.5V) J20.6(1.5V) J20.28(1.5V) J20.48(1.5V) ; also on sheet 26
1V8: C729.1 C730.1 FB50.1 R502.1 R504.1 R506.1 R508.1 ; also on sheet 6 7 8 9 13 14 27
1V8_0641_VDD: C1049.1 C1050.1 C1051.1 FB55.2 R839.1 R841.1 U97.16(VDD1.8) U97.31(VDD1.8)
1V8_0641_VDDA: C736.1 C737.1 R841.2 U97.26(VDDA1.8)
1V8_0641_VDDIO: C1044.1 C1045.1 C1046.1 C1047.1 C1048.1 C1052.1 FB54.1 U97.5(VDDREF1.8) U97.12(VDDIO) U97.17(VDDIO) U97.27(VDDIO) U97.32(VDDIO) U97.39(VDDIO)
1V8_0641_VDDXTAL: C1040.1 C1041.1 R839.2 U97.4(VDDXTAL1.8)
1V8_OSC_USB: C135.1 C136.1 FB10.2 X1.4(VDD)
1V8_SLP: C133.1 C134.1 C698.1 C699.1 C700.1 C711.1 C712.1 C713.1 C714.1 C715.1 C716.1 C720.1 C721.1 C735.1 C1101.1 C1104.1 C1105.1 FB10.1 FB48.1 FB54.2 FB55.1 R829.1 R834.1 R843.1 R844.1 U65.A3(VCCIO2) U65.A14(VCCIO2) U65.C16(VCCIO2) U65.F8(VCCIO2) U65.F9(VCCIO2) U65.H8(VCCINT) U65.H10(VCCINT) U65.H11(VCCIO2) U65.J7(VCCINT) U65.J9(VCCINT) U65.J11(VCCIO2) U65.P16(VCCIO2) U97.11(VDDDIG1.8) ; also on sheet 9 13 14 26 27
1V8_XGT1_VREGSRDS: C1177.1 C1178.1 C1179.1 C1180.1 U101.T4(P0_VREG_SRDS) U101.T6(P0_VREG_SRDS)
2V1: C1136.1 C1137.1 C1138.1 C1139.1 C1140.1 C1141.1 C1142.1 C1151.1 C1152.1 C1153.1 FB58.2 FB68.2 U101.A3(VA22) U101.A5(VA22) U101.A7(VA22) U101.A9(VA22) U101.C3(VA22) U101.C5(VA22) U101.C7(VA22) U101.C9(VA22) ; also on sheet 1 25
2V1_XGT1_VDDSRDS: C1181.1 C1183.1 C1184.1 C1185.1 FB68.1 U101.P4(V22_SRDS) U101.R3(V22_SRDS)
2V1_XGT1_XTAL: C1193.1 C1194.1 FB58.1 U101.E18(VA22_XTAL)
2V5: C1121.1 C1186.2 C1187.2 C1188.2 C1189.2 C1190.2 FB59.2 FB67.2 J51.6 R884.2 R886.1 R897.2 R941.2 R942.2 R943.2 U101.E3(VDD_FLASH) U101.J3(VDD_IO) U101.K4(VDD_IO) U101.K16(VDD_IO) U101.L16(VDD_IO) U102.3(~{WP}) U102.7(~{HOLD}) U102.8(VCC) ; also on sheet 1 2 10 13 17 27
3V3: C600.1 C601.1 C602.1 C603.1 C604.1 C605.1 C626.1 C627.1 C628.1 C629.1 C742.1 C743.1 C1375.1 C1376.1 C1377.1 FB52.1 FB70.1 FB71.1 J18.A9(+3V3) J18.A10(+3V3) J18.B8(+3V3) J18.B10(+3V3AUX) J19.2(3.3V) J19.24(3.3VAUX) J19.52(3.3V) J20.2(3.3V) J20.24(3.3VAUX) J20.52(3.3V) R398.2 R399.2 R402.2 R403.2 R404.2 R405.2 R406.2 R407.2 R408.2 R409.2 R410.2 R411.2 R549.1 R988.1 R989.1 R990.1 R991.1 R992.1 R994.1 R996.1 R998.1 U68.10(VCC) U68.16(VCC) U110.1(VDD) U110.6(VDD) U110.10(VDD) ; also on sheet 7 8 9 11 12 13 15 17 27
3V3_859S0212I_1: C1390.1 C1391.1 FB70.2 U113.9(VCC_TAP) U113.16(VCC)
3V3_859S0212I_2: C1392.1 C1393.1 FB71.2 U112.9(VCC_TAP) U112.16(VCC)
3V3_OSC_CPLD: C703.1 C704.1 FB47.2 R494.1 X2.4(VDD)
3V3_PGOOD: U65.K1(IO_B1) ; also on sheet 26
3V3_SLP: C701.1 C702.1 C705.1 C706.1 C707.1 C708.1 C709.1 C710.1 C1102.1 C1103.1 FB47.1 J26.4 R497.1 R498.1 R1016.2 U65.C1(VCCIO1) U65.H6(VCCIO1) U65.J6(VCCIO1) U65.L8(VCCIO1) U65.L9(VCCIO1) U65.P1(VCCIO1) U65.T3(VCCIO1) U65.T14(VCCIO1) ; also on sheet 5 9 15 16 25 26 27 28
3V3A_843002: C750.1 C751.1 R549.2 U68.8(VCCA)
3V3O_843002: C746.1 C747.1 FB52.2 U68.2(VCCO) U68.20(VCCO)
12V: C620.1 C621.1 C622.1 C623.1 C624.1 C625.1 J18.A2(+12V) J18.A3(+12V) J18.B1(+12V) J18.B2(+12V) J18.B3(+12V) ; also on sheet 11 27 28
GND: C132.2 C133.2 C134.2 C135.2 C136.2 C600.2 C601.2 C602.2 C603.2 C604.2 C605.2 C609.2 C610.2 C611.2 C612.2 C613.2 C614.2 C620.2 C621.2 C622.2 C623.2 C624.2 C625.2 C626.2 C627.2 C628.2 C629.2 C698.2 C699.2 C700.2 C701.2 C702.2 C703.2 C704.2 C705.2 C706.2 C707.2 C708.2 C709.2 C710.2 C711.2 C712.2 C713.2 C714.2 C715.2 C716.2 C718.2 C720.2 C721.2 C722.2 C723.2 C728.2 C729.2 C730.2 C731.2 C732.2 C733.2 C734.2 C735.2 C736.2 C737.2 C738.2 C739.2 C742.2 C743.2 C746.2 C747.2 C750.2 C751.2 C1040.2 C1041.2 C1044.2 C1045.2 C1046.2 C1047.2 C1048.2 C1049.2 C1050.2 C1051.2 C1052.2 C1101.2 C1102.2 C1103.2 C1104.2 C1105.2 C1119.2 C1120.2 C1121.2 C1122.1 C1123.1 C1124.2 C1125.1 C1126.2 C1127.2 C1128.2 C1129.2 C1130.2 C1131.1 C1132.1 C1133.1 C1134.1 C1135.1 C1136.2 C1137.2 C1138.2 C1139.2 C1140.2 C1141.2 C1142.2 C1143.1 C1144.1 C1145.2 C1146.1 C1147.2 C1148.1 C1149.2 C1150.1 C1151.2 C1152.2 C1153.2 C1154.1 C1155.1 C1156.1 C1157.1 C1158.1 C1159.1 C1160.2 C1161.2 C1162.2 C1163.2 C1164.2 C1165.2 C1166.1 C1167.2 C1168.2 C1169.1 C1170.1 C1171.1 C1172.1 C1173.1 C1174.1 C1175.1 C1176.1 C1177.2 C1178.2 C1179.2 C1180.2 C1181.2 C1182.1 C1183.2 C1184.2 C1185.2 C1186.1 C1187.1 C1188.1 C1189.1 C1190.1 C1191.2 C1192.2 C1193.2 C1194.2 C1197.2 C1198.1 C1199.1 C1200.2 C1201.1 C1202.1 C1203.2 C1204.1 C1205.1 C1206.1 C1365.2 C1366.1 C1367.1 C1368.2 C1369.1 C1370.1 C1371.2 C1372.1 C1373.1 C1374.1 C1375.2 C1376.2 C1377.2 C1390.2 C1391.2 C1392.2 C1393.2 J18.A1(~{PRSNT1}) J18.A4(GND) J18.A12(GND) J18.A15(GND) J18.A18(GND) J18.B4(GND) J18.B7(GND) J18.B13(GND) J18.B16(GND) J18.B18(GND) J19.4(GND) J19.9(GND) J19.15(GND) J19.18(GND) J19.21(GND) J19.26(GND) J19.27(GND) J19.29(GND) J19.34(GND) J19.35(GND) J19.40(GND) J19.50(GND) J19.53(MS1) J19.54(MS2) J20.4(GND) J20.9(GND) J20.15(GND) J20.18(GND) J20.21(GND) J20.26(GND) J20.27(GND) J20.29(GND) J20.34(GND) J20.35(GND) J20.40(GND) J20.50(GND) J20.53(MS1) J20.54(MS2) J26.2 J26.10 J51.7 J52.1 J60.1 J61.2 M3.1 M4.1 M5.1 M6.1 M7.1 M8.1 M9.1 M10.1 M11.1 M12.1 M13.1 M14.1 M15.1 M16.1 M17.1 M18.1 R176.1 R400.2 R401.2 R496.1 R499.2 R500.2 R501.2 R503.2 R505.2 R507.2 R509.2 R513.1 R518.1 R519.2 R523.2 R524.1 R527.2 R528.1 R534.2 R535.1 R538.1 R541.1 R542.1 R543.1 R544.1 R835.2 R838.2 R842.1 R888.2 R889.2 R890.2 R891.2 R892.2 R899.2 R900.2 R901.1 R950.1 R979.1 R993.2 R995.2 R997.2 R999.2 R1000.2 R1001.2 R1002.2 R1003.2 R1004.1 R1005.1 R1006.1 R1007.1 R1008.1 R1009.1 R1010.1 R1011.1 R1013.2 R1014.1 SW3.9 U65.A1(GNDIO) U65.A16(GNDIO) U65.B2(GNDIO) U65.B15(GNDIO) U65.G7(GNDIO) U65.G8(GNDIO) U65.G9(GNDIO) U65.G10(GNDIO) U65.H7(GNDINT) U65.H9(GNDINT) U65.J8(GNDINT) U65.J10(GNDINT) U65.K7(GNDIO) U65.K8(GNDIO) U65.K9(GNDIO) U65.K10(GNDIO) U65.R2(GNDIO) U65.R15(GNDIO) U65.T1(GNDIO) U65.T16(GNDIO) U68.17(VEE) U97.8(GNDDIG) U97.41(EPAD) U101.A1(RG) U101.A18(RG) U101.B3(AVSS) U101.B5(AVSS) U101.B7(AVSS) U101.B9(AVSS) U101.B12(AVSS) U101.B14(AVSS) U101.B16(AVSS) U101.C2(AVSS) U101.C4(AVSS) U101.C6(AVSS) U101.C8(AVSS) U101.C11(AVSS) U101.C13(AVSS) U101.C15(AVSS) U101.C17(AVSS) U101.D3(AVSS) U101.D5(AVSS) U101.D7(AVSS) U101.D9(AVSS) U101.D12(AVSS) U101.D14(AVSS) U101.D16(AVSS) U101.D18(AVSS) U101.E1(DC_MASTER_N) U101.E4(AVSS) U101.E6(AVSS_PLL) U101.E11(AVSS) U101.E13(AVSS) U101.E15(AVSS) U101.E17(AVSS) U101.F6(AVSS) U101.F8(AVSS) U101.F10(AVSS) U101.F12(AVSS) U101.G5(AVSS) U101.G7(AVSS) U101.G9(AVSS) U101.G11(AVSS) U101.H4(MDIO_1P2_SELECT_N) U101.H6(AVSS) U101.H8(AVSS) U101.H10(AVSS) U101.H12(AVSS) U101.J5(VSS) U101.J7(VSS) U101.J9(VSS) U101.J11(VSS) U101.J13(VSS) U101.K6(VSS) U101.K8(VSS) U101.K10(VSS) U101.K12(VSS) U101.L4(RG) U101.L7(VSS) U101.L9(VSS) U101.L11(VSS) U101.L13(VSS) U101.M6(VSS) U101.M8(VSS) U101.M10(VSS) U101.M12(VSS) U101.N1(VSS_SRDS) U101.N2(VSS_SRDS) U101.N5(VSS) U101.N7(VSS) U101.N9(VSS) U101.N11(VSS) U101.N13(VSS) U101.P3(VSS_SRDS) U101.P6(VSS) U101.P8(VSS) U101.P10(VSS) U101.P12(VSS) U101.P17(VSS_SRDS) U101.P18(VSS_SRDS) U101.R1(VSS_SRDS) U101.R2(VSS_SRDS) U101.R4(VSS_SRDS) U101.R6(VSS_SRDS) U101.R7(VSS) U101.R9(VSS) U101.R11(VSS) U101.R13(VSS) U101.R14(VSS_SRDS) U101.T3(VSS_SRDS) U101.T5(VSS_SRDS) U101.T7(VSS_SRDS) U101.T9(VSS_SRDS) U101.T11(VSS_SRDS) U101.T13(VSS_SRDS) U101.T15(VSS_SRDS) U101.U1(VSS_SRDS) U101.U5(VSS_SRDS) U101.U9(VSS_SRDS) U101.U11(VSS_SRDS) U101.U16(VSS_SRDS) U101.U18(VSS_SRDS) U101.V5(VSS_SRDS) U101.V9(VSS_SRDS) U101.V11(VSS_SRDS) U101.V16(VSS_SRDS) U102.4(GND) U110.2(PD) U110.5(GND) U110.11(GND) U110.20(GND) U110.21(EPAD) U112.10(VEE) U112.15(VEE) U113.10(VEE) U113.15(VEE) X1.2(GND) X2.2(GND) X3.2(GND) X5.2(GND) Y4.2 Y4.4 Y5.2 Y5.4 Y7.2 Y7.4 ; also on sheet 1 2 5 6 7 8 9 10 11 12 13 14 15 16 17 25 26 27 28 29
VDD_EN: U65.N5(IO_B1) ; also on sheet 27
VDD_EN_N: U65.N12(IO_B1) ; also on sheet 25
VDD_SD_SENSE: U65.D3(IO_B1) ; also on sheet 8
BOOT_FLASH_SEL: R502.2 SW3.4 U65.F15(IO_B2)
CFG_VBANK0: R504.2 SW3.5 U65.J16(IO_B2) ; also on sheet 7
CFG_VBANK1: R506.2 SW3.6 U65.H16(IO_B2) ; also on sheet 7
CFG_VBANK2: R508.2 SW3.7 U65.J15(IO_B2) ; also on sheet 7
CKE_ISO_EN: U65.L4(IO_B1) ; also on sheet 27
COP_HRESET_N: U65.G1(IO_B1) ; also on sheet 9
COP_SRESET_N: U65.H1(IO_B1) ; also on sheet 9
COP_TRST_N: U65.J1(IO_B1) ; also on sheet 9
CPLD_INT_N: U65.E13(IO_B2) ; also on sheet 9
CPLD_REFCLK: R495.2 U65.H5(GCLK0p)
CPLD_TCK: J26.1 R496.2 U65.P3(TCK)
CPLD_TDI: J26.9 R498.2 U65.L6(TDI)
CPLD_TDO: J26.3 U65.M5(TDO)
CPLD_TMS: J26.5 R497.2 U65.N4(TMS)
DDR_REFCLK: R517.2 R518.2 ; also on sheet 9
DDR_RST_N: U65.A2(IO_B2) ; also on sheet 5
DDRPWR_EN: U65.P4(IO_B1) ; also on sheet 27
DDRPWR_EN_N: U65.R4(IO_B1) ; also on sheet 27
DIFSYSCLK_OE_N: R844.2 U65.N15(IO_B2) U97.38(~{OE5})
EARTH: C1205.2 C1206.2 C1373.2 C1374.2 J50.20 J50.21 J56.20 J56.21 ; also on sheet 12 15 16 17 29
EC1_PME_N: U65.P13(IO_B1) ; also on sheet 9 16
EC1_RST_N: U65.H3(IO_B1) ; also on sheet 16
EC2_RST_N: U65.J2(IO_B1) ; also on sheet 17
EMI2_MDC: J60.3 U101.J18(MDC) ; also on sheet 2 10
EMI2_MDIO: J60.2 U101.L18(MDIO) ; also on sheet 2 10
ETH_REFCLK1_N: C1384.1 R543.2 U68.4(~{Q0})
ETH_REFCLK1_P: C1382.1 R544.2 U68.3(Q0)
ETH_REFCLK2_N: C1389.1 R541.2 U68.18(~{Q1})
ETH_REFCLK2_P: C1387.1 R542.2 U68.19(Q1)
ETH_REFCLK_SEL: U65.T12(IO_B1) U68.9(F_SEL0)
EVDD_SEL: U65.F1(IO_B1) ; also on sheet 27
EVT_BRD_ISO: U65.K16(IO_B2) ; also on sheet 9
EVT_PWR_EN: U65.L15(IO_B2) ; also on sheet 9
EVT_PWR_OK: U65.L16(IO_B2) ; also on sheet 9
FAN_PWM: U65.E1(IO_B1) ; also on sheet 28
HRESET_N: U65.D14(IO_B2) ; also on sheet 9
I2C1_SCL_SLP: U97.9(SCLK_3.3) ; also on sheet 5 9 15 25
I2C1_SDA_SLP: U97.10(SDATA_3.3) ; also on sheet 5 9 15 25
I2C2_MPEX1_SCL: J19.30(SMB_CLK) R398.1 ; also on sheet 9
I2C2_MPEX1_SDA: J19.32(SMB_DATA) R404.1 ; also on sheet 9
I2C2_MPEX2_SCL: J20.30(SMB_CLK) R409.1 ; also on sheet 9
I2C2_MPEX2_SDA: J20.32(SMB_DATA) R410.1 ; also on sheet 9
I2C2_PEX_SCL: J18.B5(SMCLK) R406.1 ; also on sheet 9
I2C2_PEX_SDA: J18.B6(SMDAT) R407.1 ; also on sheet 9
IFC_A16: U65.D16(IO_B2) ; also on sheet 6 7
IFC_A17: U65.E15(IO_B2) ; also on sheet 6 7
IFC_A18: U65.F14(IO_B2) ; also on sheet 6 7
IFC_A19: U65.F13(IO_B2) ; also on sheet 6 7
IFC_A21: U65.C10(IO_B2) ; also on sheet 6 7
IFC_A27: U65.C13(IO_B2) ; also on sheet 6 7
IFC_A28: U65.C12(IO_B2) ; also on sheet 6 7
IFC_A29: U65.C11(IO_B2) ; also on sheet 6 7
IFC_A30: U65.D12(IO_B2) ; also on sheet 6 7
IFC_A31: U65.A5(IO_B2) ; also on sheet 6
IFC_AD0: U65.A13(IO_B2) ; also on sheet 6 7
IFC_AD1: U65.B13(IO_B2) ; also on sheet 6 7
IFC_AD2: U65.B12(IO_B2) ; also on sheet 6 7
IFC_AD3: U65.A12(IO_B2) ; also on sheet 6 7
IFC_AD4: U65.A11(IO_B2) ; also on sheet 6 7
IFC_AD5: U65.B11(IO_B2) ; also on sheet 6 7
IFC_AD6: U65.B10(IO_B2) ; also on sheet 6 7
IFC_AD7: U65.A10(IO_B2) ; also on sheet 6 7
IFC_AD8: U65.A6(IO_B2) ; also on sheet 6 7
IFC_AD9: U65.B7(IO_B2) ; also on sheet 6 7
IFC_AD10: U65.A7(IO_B2) ; also on sheet 6 7
IFC_AD11: U65.B8(IO_B2) ; also on sheet 6 7
IFC_AD12: U65.A8(IO_B2) ; also on sheet 6 7
IFC_AD13: U65.C8(IO_B2) ; also on sheet 6 7
IFC_AD14: U65.A9(IO_B2) ; also on sheet 6 7
IFC_AD15: U65.B9(IO_B2) ; also on sheet 6 7
IFC_AVD: U65.C9(IO_B2) ; also on sheet 6 7
IFC_CLE: U65.D15(IO_B2) ; also on sheet 6 7
IFC_CLK: U65.J12(GCLK2p) ; also on sheet 6
IFC_CS0_N: U65.B6(IO_B2) ; also on sheet 6
IFC_CS1_N: U65.B5(IO_B2) ; also on sheet 6
IFC_CS2_N: U65.A4(IO_B2) ; also on sheet 6
IFC_OE_N: SW3.2 U65.G15(IO_B2) ; also on sheet 6 7
IFC_RB0_N: U65.A15(IO_B2) ; also on sheet 6
IFC_RB1_N: U65.B16(IO_B2) ; also on sheet 6
IFC_TE: U65.D11(IO_B2) ; also on sheet 6
IFC_WE_N: SW3.1 U65.H15(IO_B2) ; also on sheet 6 7
IFC_WP_N: SW3.3 U65.F16(IO_B2) ; also on sheet 6 7
IO_B1: U65.B1(IO_B2)
IO_B3: U65.B3(IO_B2)
IO_B14: U65.B14(IO_B2)
IO_C4: U65.C4(IO_B2)
IO_C5: U65.C5(IO_B2)
IO_C6: U65.C6(IO_B2)
IO_D4: U65.D4(IO_B2)
IO_D5: U65.D5(IO_B2)
IO_E2: U65.E2(IO_B1)
IO_E3: U65.E3(IO_B1)
IO_E4: U65.E4(IO_B1)
IO_F2: U65.F2(IO_B1)
IO_F3: U65.F3(IO_B1)
IO_G2: U65.G2(IO_B1)
IO_G3: U65.G3(IO_B1)
IO_G14: U65.G14(IO_B2)
IO_H2: U65.H2(IO_B1)
IO_H14: U65.H14(IO_B2)
IO_J3: U65.J3(IO_B1)
IO_J14: U65.J14(IO_B2)
IO_K2: U65.K2(IO_B1)
IO_K3: U65.K3(IO_B1)
IO_K14: U65.K14(IO_B2)
IO_L1: U65.L1(IO_B1)
IO_L2: U65.L2(IO_B1)
IO_L3: U65.L3(IO_B1)
IO_L13: U65.L13(IO_B2)
IO_L14: U65.L14(IO_B2)
IO_M1: U65.M1(IO_B1)
IO_M3: U65.M3(IO_B1)
IO_M13: U65.M13(IO_B2)
IO_M14: U65.M14(IO_B2)
IO_N2: U65.N2(IO_B1)
IO_N3: U65.N3(IO_B1)
IO_N13: U65.N13(IO_B2)
IO_P2: U65.P2(IO_B1)
IO_P8: U65.P8(IO_B1)
IO_P14: U65.P14(IO_B2)
IO_R1: U65.R1(IO_B1)
IO_R6: U65.R6(IO_B1)
IO_R7: U65.R7(IO_B1)
IO_R9: U65.R9(IO_B1)
IO_R10: U65.R10(IO_B1)
IO_R16: U65.R16(IO_B1)
IO_T4: U65.T4(IO_B1)
IO_T5: U65.T5(IO_B1)
IO_T6: U65.T6(IO_B1)
IO_T7: U65.T7(IO_B1)
IO_T8: U65.T8(IO_B1)
IO_T9: U65.T9(IO_B1)
IO_T10: J61.1 R1016.1 U65.T10(IO_B1)
IO_T11: U65.T11(IO_B1)
IO_T15: U65.T15(IO_B1)
IOPWR_EN: U65.R8(IO_B1) ; also on sheet 25 26 27
IOPWR_EN_N: U65.P10(IO_B1) ; also on sheet 27
JTAG_TRST_N: U65.B4(IO_B2) ; also on sheet 9
LED_STATUS: U65.D2(IO_B1) ; also on sheet 28
MPEX1_REFCLK_N: J19.13(REFCLK+) R526.2 R528.2
MPEX1_REFCLK_P: J19.11(REFCLK-) R524.2 R525.2
MPEX1_RST_N: J19.22(~{PERST}) U65.T2(IO_B1)
MPEX1_RX_N: C1266.2 ; also on sheet 10
MPEX1_RX_P: C1265.2 ; also on sheet 10
MPEX1_TX_N: C599.2 ; also on sheet 10
MPEX1_TX_P: C598.2 ; also on sheet 10
MPEX2_REFCLK_N: J20.13(REFCLK+) R532.2 R534.1
MPEX2_REFCLK_P: J20.11(REFCLK-) R527.1 R530.2
MPEX2_RST_N: J20.22(~{PERST}) U65.R3(IO_B1)
MPEX2_RX_N: C1270.2 ; also on sheet 10
MPEX2_RX_P: C1269.2 ; also on sheet 10
MPEX2_TX_N: C631.2 ; also on sheet 10
MPEX2_TX_P: C630.2 ; also on sheet 10
NAND_CS_N: U65.G16(IO_B2) ; also on sheet 7
NAND_RB_N: U65.C7(IO_B2) ; also on sheet 7
NOR_CS_N: U65.D13(IO_B2) ; also on sheet 7
NOR_RB_N: U65.E14(IO_B2) ; also on sheet 7
NOR_RST_N: U65.C14(IO_B2) ; also on sheet 7
OVDD_OSC_DDR: C731.1 C732.1 FB50.2 X5.4(VDD)
OVDD_OSC_SYS: C722.1 C723.1 FB48.2 X3.4(VDD)
PCIE_REFCLK1_N: C1386.1 R1012.2 R1013.1
PCIE_REFCLK1_P: C1388.1 R1014.2 R1015.2
PCIE_REFCLK2_N: C1383.1 R537.2 R538.2
PCIE_REFCLK2_P: C1385.1 R535.2 R536.2
PEX_PRS_N: J18.B17(~{PRSNT2}_X1) R405.1 U65.P5(IO_B1)
PEX_REFCLK_N: J18.A14(REFCLK-) R521.2 R523.1
PEX_REFCLK_P: J18.A13(REFCLK+) R519.1 R520.2
PEX_RST_N: J18.A11(~{PERST}) U65.R5(IO_B1)
PEX_RX_N: J18.A17(PERN0) U110.17(B1+)
PEX_RX_P: J18.A16(PERP0) U110.16(B1-)
PEX_SEL_N: R979.2 U65.P6(IO_B1) U110.9(SEL)
PEX_TX_N: C607.2 U110.18(B0-)
PEX_TX_P: C606.2 U110.19(B0+)
PEXCLK_OE_N: R843.2 U65.N16(IO_B2) U97.13(~{OE0}) U97.21(~{OE1}) U97.24(~{OE2}) U97.30(~{OE3}) U97.35(~{OE4})
PORESET_N: U65.C15(IO_B2) ; also on sheet 9
PWR_GOOD: U65.C2(IO_B1) ; also on sheet 28
PWR_RST_N: U65.C3(IO_B1) ; also on sheet 28
RESET_REQ_N: U65.K15(IO_B2) ; also on sheet 9
RTC_INT_N: U65.P9(IO_B1) ; also on sheet 15
SD_REFCLK1_N: R997.1 U113.14(Q0) ; also on sheet 10
SD_REFCLK1_P: R993.1 U113.13(~{Q0}) ; also on sheet 10
SD_REFCLK2_N: R995.1 U112.13(~{Q0}) ; also on sheet 10
SD_REFCLK2_P: R999.1 U112.14(Q0) ; also on sheet 10
SD_REFCLK_SEL: U65.T13(IO_B1) U112.1(CLK_SEL) U113.1(CLK_SEL)
SD_RX1_N: U110.7(A1+) ; also on sheet 10
SD_RX1_P: U110.8(A1-) ; also on sheet 10
SD_TX1_N: U110.4(A0-) ; also on sheet 10
SD_TX1_P: U110.3(A0+) ; also on sheet 10
SDHC_VS: U65.M16(IO_B2) ; also on sheet 9 14
SENSEVDD_EN_N: U65.P7(IO_B1) ; also on sheet 25
SGMII_RX_N: U110.13(C1+) ; also on sheet 2
SGMII_RX_P: U110.12(C1-) ; also on sheet 2
SGMII_TX_N: U110.14(C0-) ; also on sheet 2
SGMII_TX_P: U110.15(C0+) ; also on sheet 2
SYS_REFCLK: R511.2 R513.2 ; also on sheet 9
SYS_REFCLK_N: R837.2 R838.1 ; also on sheet 9
SYS_REFCLK_P: R835.1 R836.2 ; also on sheet 9
SYSCLK_OE: U65.M15(IO_B2) X1.1(OE) X3.1(OE) X5.1(OE)
TDMR1_INT_N: U65.R12(IO_B1) ; also on sheet 11
TDMR2_INT_N: U65.P11(IO_B1) ; also on sheet 11
TDMR_PRS_N: U65.P12(IO_B1) ; also on sheet 11
TDMR_RST_N: U65.R11(IO_B1) ; also on sheet 11
TDMR_SLP_N: U65.R13(IO_B1) ; also on sheet 11
TEST_SEL_N: SW3.8 U65.E16(IO_B2) ; also on sheet 9
THERM_ALERT_N: U65.M4(IO_B1) ; also on sheet 15
THERM_FAULT_N: U65.D1(IO_B1) ; also on sheet 15 28
USB_REFCLK: R175.2 R176.2 ; also on sheet 9 14
VCORE_EN: U65.R14(IO_B1) ; also on sheet 25
XFI_RX_N: U101.V6(TX_LN2_N) ; also on sheet 10
XFI_RX_P: U101.U6(TX_LN2_P) ; also on sheet 10
XFI_TX_N: C1117.1 ; also on sheet 10
XFI_TX_P: C1118.1 ; also on sheet 10
XGT1_CM_N: J50.15 U101.D8(CM_N)
XGT1_CM_P: J50.14 U101.E8(CM_P)
XGT1_INT_N: R884.1 R885.2 U65.M2(IO_B1)
XGT1_LED_GRN: R902.2 U101.K1(LED0)
XGT1_LED_YEL: R903.2 U101.L1(LED1)
XGT1_MDI0_N: J50.9 U101.A2(A_N)
XGT1_MDI0_P: J50.8 U101.B2(A_P)
XGT1_MDI1_N: J50.3 U101.A4(B_N)
XGT1_MDI1_P: J50.2 U101.B4(B_P)
XGT1_MDI2_N: J50.5 U101.A6(C_N)
XGT1_MDI2_P: J50.4 U101.B6(C_P)
XGT1_MDI3_N: J50.11 U101.A8(D_N)
XGT1_MDI3_P: J50.10 U101.B8(D_P)
XGT1_RST_N: R896.1 U65.P15(IO_B2)
XGT1_SPI_CS_N: R943.1 U101.G2(CE_N) U102.1(~{CS})
XGT1_SPI_SCLK: U101.G1(SCLK) U102.6(SCK)
XGT1_SPI_SDI: U101.F2(SOUT) U102.5(SI)
XGT1_SPI_SDO: U101.F1(SIN) U102.2(SO)
XGT1_TCK: J51.3 U101.K14(TCK)
XGT1_TDI: J51.1 U101.L14(TDI)
XGT1_TDO: J51.5 U101.L15(TDO)
XGT1_TMS: J51.2 U101.M16(TMS)
XGT1_TRST_N: J51.4 R950.2 U101.M15(TRST_N)
XGT2_CM_N: J56.15 ; also on sheet 2
XGT2_CM_P: J56.14 ; also on sheet 2
XGT2_INT_N: U65.N1(IO_B1) ; also on sheet 2
XGT2_LED_GRN: R977.2 ; also on sheet 2
XGT2_LED_YEL: R978.2 ; also on sheet 2
XGT2_MDI0_N: J56.9 ; also on sheet 2
XGT2_MDI0_P: J56.8 ; also on sheet 2
XGT2_MDI1_N: J56.3 ; also on sheet 2
XGT2_MDI1_P: J56.2 ; also on sheet 2
XGT2_MDI2_N: J56.5 ; also on sheet 2
XGT2_MDI2_P: J56.4 ; also on sheet 2
XGT2_MDI3_N: J56.11 ; also on sheet 2
XGT2_MDI3_P: J56.10 ; also on sheet 2
XGT2_RST_N: U65.N14(IO_B2) ; also on sheet 2
N16980127: J18.B11(~{WAKE}) R408.1
N16980167: J18.A8(JTAG5_TMS) R403.1
N16980179: J18.B9(JTAG1_~{TRST}) R400.1
N16980191: J18.A5(JTAG2_TCK) R401.1
N16980203: J18.A6(JTAG3_TDI) R402.1
N16980532: C607.1 J18.B15(PETN0)
N16980534: C606.1 J18.B14(PETP0)
N16984231: C598.1 J19.33(PETP0)
N16984233: C599.1 J19.31(PETN0)
N16984263: C1265.1 J19.25(PERP0)
N16984265: C1266.1 J19.23(PERN0)
N16985354: C630.1 J20.33(PETP0)
N16985356: C631.1 J20.31(PETN0)
N16985386: C1269.1 J20.25(PERP0)
N16985388: C1270.1 J20.23(PERN0)
N17111815: J19.1(~{WAKE}) R399.1
N17112169: J20.1(~{WAKE}) R411.1
N17170143: C718.1 R511.1 X3.3(OUT)
N17232338: C728.1 R517.1 X5.3(OUT)
N18382428: R499.1 SW3.16
N18382505: R500.1 SW3.15
N18382570: R501.1 SW3.14
N18382580: R503.1 SW3.13
N18382664: R507.1 SW3.11
N18382676: R509.1 SW3.10
N18848286: C1117.2 U101.V4(RX_LN2_N)
N18848288: C1118.2 U101.U4(RX_LN2_P)
N18849311: R885.1 U101.K18(INT_N)
N18850569: R897.1 U101.H3(RST_OUT_N)
N18882897: R901.2 U101.A10(RREF_BG)
N19017659: C1198.2 C1199.2 C1201.2 C1202.2 C1204.2 J50.1 J50.6 J50.7 J50.12 J50.13
N19034153: C1200.1 J50.16 R902.1
N19034169: C1197.1 FB59.1 J50.17 J50.19
N19034241: C1203.1 J50.18 R903.1
N19126530: R505.1 SW3.12
N19163046: R495.1 X2.3(OUT)
N19163064: R494.2 X2.1(OE)
N23146172: R520.1 U97.14(DIF0)
N23146174: R521.1 U97.15(~{DIF0})
N23146290: C733.1 U97.2(X1_25) Y4.1
N23146296: C734.1 U97.3(X2) Y4.3
N23146369: R525.1 U97.22(DIF2)
N23146371: R526.1 U97.23(~{DIF2})
N23146377: R530.1 U97.28(DIF3)
N23146379: R532.1 U97.29(~{DIF3})
N23146385: R536.1 U97.33(DIF4)
N23146387: R537.1 U97.34(~{DIF4})
N23146565: R837.1 U97.37(~{DIF5})
N23146571: R836.1 U97.36(DIF5)
N23146840: R829.2 R842.2 U97.1(SS_EN_TRI)
N23147063: R834.2 U97.6(SADR/REF1.8)
N23147551: C132.1 R175.1 X1.3(OUT)
N23148282: C739.1 U68.13(XTAL_IN) Y5.1
N23148288: C738.1 U68.12(XTAL_OUT) Y5.3
N23238405: C1119.1 R898.1 Y7.1
N23238411: C1120.1 U101.F18(XTAL_I) Y7.3
N23238429: R898.2 U101.G18(XTAL_O)
N23238970: R886.2 U101.N17(RX_DC_RST_N)
N23239280: R889.1 U101.J15(ADDR1)
N23239284: R892.1 U101.G17(ADDR4)
N23239286: R891.1 U101.H16(ADDR3)
N23239292: R890.1 U101.J16(ADDR2)
N23239393: R888.1 U101.K15(ADDR0)
N23240310: R895.2 R896.2 U101.J4(RST_N)
N23240770: R900.1 U101.F17(XTAL_SELECT_N)
N23240781: R899.1 U101.G13(50M_CLK_TERM)
N23327185: R887.2 U101.F5(TX_EN)
N23503182: J52.3 R942.1 U101.H17(SMB_CLK)
N23503185: J52.2 R941.1 U101.H18(SMB_DAT)
N23890340: C1366.2 C1367.2 C1369.2 C1370.2 C1372.2 J56.1 J56.6 J56.7 J56.12 J56.13
N23890653: C1368.1 J56.16 R977.1
N23890655: C1365.1 FB67.1 J56.17 J56.19
N23890663: C1371.1 J56.18 R978.1
N24117705: R1015.1 U97.18(DIF1)
N24117707: R1012.1 U97.19(~{DIF1})
N24120812: C1382.2 R990.2 R1008.2 U113.3(~{PCLK0})
N24120822: C1388.2 R996.2 R1004.2 U113.5(~{PCLK1})
N24120824: C1386.2 R992.2 R1006.2 U113.4(PCLK1)
N24120892: C1384.2 R988.2 R1010.2 U113.2(PCLK0)
N24121080: R1000.1 U113.12(Q1)
N24121082: R1002.1 U113.11(~{Q1})
N24122901: C1385.2 R991.2 R1009.2 U112.3(~{PCLK0})
N24122903: C1389.2 R998.2 R1005.2 U112.5(~{PCLK1})
N24122905: C1387.2 R994.2 R1007.2 U112.4(PCLK1)
N24122973: C1383.2 R989.2 R1011.2 U112.2(PCLK0)
N24123129: R1001.1 U112.12(Q1)
N24123131: R1003.1 U112.11(~{Q1})

Not connected (* = marked no-connect by the designer): J18 A7(JTAG4_TDO)* B12(RSVD1)*; J19 3(RSVD1)* 5(RSVD2)* 7(~{CLKREQ})* 8(RSVD3)* 10(RSVD4)* 12(RSVD5)* 14(RSVD6)* 16(RSVD7)* 17(RSVD8)* 19(RSVD9)* 20(RSVD10)* 36(USB_D-)* 37(RSVD11)* 38(USB_D+)* 39(RSVD12)* 41(RSVD13)* 42(~{LED_WWAN})* 43(RSVD14)* 44(~{LED_WLAN})* 45(RSVD15)* 46(~{LED_WPAN})* 47(RSVD16)* 49(RSVD17)* 51(RSVD18)*; J20 3(RSVD1)* 5(RSVD2)* 7(~{CLKREQ})* 8(RSVD3)* 10(RSVD4)* 12(RSVD5)* 14(RSVD6)* 16(RSVD7)* 17(RSVD8)* 19(RSVD9)* 20(RSVD10)* 36(USB_D-)* 37(RSVD11)* 38(USB_D+)* 39(RSVD12)* 41(RSVD13)* 42(~{LED_WWAN})* 43(RSVD14)* 44(~{LED_WLAN})* 45(RSVD15)* 46(~{LED_WPAN})* 47(RSVD16)* 49(RSVD17)* 51(RSVD18)*; J26 6* 7* 8*; U65 D6(NC)* D7(NC)* D8(NC)* D9(NC)* D10(NC)* E5(NC)* E6(NC)* E7(NC)* E8(NC)* E9(NC)* E10(NC)* E11(NC)* E12(NC)* F4(NC)* F5(NC)* F6(NC)* F7(NC)* F10(NC)* F11(NC)* F12(NC)* G4(NC)* G5(NC)* G6(NC)* G11(NC)* G12(NC)* G13(NC)* H4(NC)* H12(GCLK3p)* H13(NC)* J4(NC)* J5(GCLK1p)* J13(NC)* K4(NC)* K5(NC)* K6(NC)* K11(NC)* K12(NC)* K13(NC)* L5(NC)* L7(NC)* L10(NC)* L11(NC)* L12(NC)* M6(NC)* M7(NC)* M8(DEV_OE)* M9(DEV_CLRn)* M10(NC)* M11(NC)* M12(NC)* N6(NC)* N7(NC)* N8(NC)* N9(NC)* N10(NC)* N11(NC)*; U68 1(NC1)* 5(MR)* 6(~{PLL_SEL})* 7(NC2)* 11(F_SEL1)* 14(TEST_CLK)* 15(~{XTAL_SEL})*; U97 7(NC1)* 20(NC2)* 25(NC3)* 40(~{CKPWRGD_PD})*; U101 A11(NC1)* A12(NC2)* A13(NC3)* A14(NC4)* A15(NC5)* A16(NC6)* A17(NC7)* B1(RNC)* B10(NC8)* B11(NC9)* B13(NC10)* B15(NC11)* B17(NC12)* B18(NC13)* C1(CLK_1588_N)* C10(RNC)* C12(NC14)* C14(NC15)* C16(NC16)* C18(NC17)* D1(CLK_1588_P)* D2(CLKO_50M_A)* D10(RNC)* D11(NC18)* D13(NC19)* D15(NC20)* D17(NC21)* E2(RNC)* E12(NC22)* E14(NC23)* E16(NC24)* F3(TDIO_N)* F4(RNC)* F7(NC25)* F9(NC26)* F11(NC27)* F13(RNC)* F14(NC28)* F15(RNC)* F16(RNC)* G3(TDIO_P)* G4(RNC)* G6(NC29)* G8(NC30)* G10(NC31)* G12(NC32)* G14(RNC)* G15(NC33)* G16(RNC)* H1(RX_DC_DATA)* H2(TX_DC_RST_N)* H5(NC34)* H7(NC35)* H9(NC36)* H11(NC37)* H13(NC38)* H14(RNC)* H15(RNC)* J1(RX_DC_CLK)* J2(RX_DC_SOF)* J14(RNC)* J17(NC39)* K2(NC40)* K3(WAKE)* K17(NC41)* L2(NC42)* L3(PERST_N)* L5(RNC)* L17(NC43)* M1(LED2)* M2(NC44)* M3(NC45)* M4(RNC)* M5(RNC)* M14(RNC)* M17(TX_DC_DATA)* M18(TX_DC_SOF)* N3(NC46)* N4(RNC)* N14(RNC)* N15(1588_SYNC)* N16(RNC)* N18(TX_DC_CLK)* P1(RX_LN0_N)* P2(RX_LN0_P)* P14(RNC)* P15(NC47)* P16(RNC)* R15(NC48)* R16(NC49)* R17(NC50)* R18(NC51)* T1(TX_LN0_N)* T2(TX_LN0_P)* T14(RNC)* T16(NC52)* T17(NC53)* T18(NC54)* U2(RX_LN1_P)* U3(TX_LN1_P)* U7(RX_LN3_P)* U8(TX_LN3_P)* U10(NC55)* U12(NC56)* U13(NC57)* U14(NC58)* U15(NC59)* U17(NC60)* V1(RNC)* V2(RX_LN1_N)* V3(TX_LN1_N)* V7(RX_LN3_N)* V8(TX_LN3_N)* V10(NC61)* V12(NC62)* V13(NC63)* V14(NC64)* V15(NC65)* V17(NC66)* V18(RNC)*; U112 6(NC)* 7(OE)* 8(SEL_OUT)*; U113 6(NC)* 7(OE)* 8(SEL_OUT)*

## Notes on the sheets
sheet 18
- 10G BASE-T PHY 1 AQR105
- LANE2 USED AS XFI MODE TO MAC
- 100 ohms
  DIFF PAIRs
- 100 ohms
  DIFF PAIRs
- PHY ADDR = 0x01
- DC_MASTER_N = 0
- (Daisy Chain Master)
- MDIO_1P2_SELECT_N = 0
- (MDIO Voltage 1.2V)
- Wake-On-LAN unused
- DEBUG HEADER
- Select Crystal
- 100 ohms
  DIFF PAIRs
- Boundry scan use only
sheet 19
- 10G BASE-T PHY 1 AQR105 POWER SUPPLY
sheet 20
- 10G/2.5G BASE-T RJ46 CONNECTORs
sheet 21
- PCIe X1 SLOT and MINI PCIe CONNECTORs
- MINI PCIe CONNECTOR
- PCIe x1 SLOT
- 100 ohms
  DIFF PAIRs
- 100 ohms
  DIFF PAIRs
- MINI PCIe CONNECTOR
- 100 ohms
  DIFF PAIRs
- 0: SELECT PCIE
- 1: SELECT SGMII
sheet 22
- CPLD
- 3.3V BANK1 IO
- 1.8V BANK2 IO
- cfg
- cfg
- cfg
- cfg
- cfg
- cfg
- cfg
- cfg
- cfg
- cfg
- cfg
- cfg
- cfg
- cfg
- OD OUTPUT
- OD OUTPUT
- OD OUTPUT
- OD OUTPUT
- SerDes Lane 0,1 Selection
- 0: XFI + PCIe
- 1: N/A + 2.5G SGMII
- Manual Selection
- cfg
- OFF: XFI + PCIe
- ON: N/A + 2.5G SGMII
- cfg
- cfg
- cfg
- cfg
- cfg
- CPLD JTAG CONNECTOR
- cfg_eng_use0
- cfg_eng_use1
- cfg_eng_use2
sheet 23
- SYSTEM CLOCK GENERATORs
- 0: 156.25MHz
  1: 125MHz
sheet 24
- SYSTEM CLOCK GENERATORs (cont.)
- LVPECL INPUT and OUTPUT
- LVPECL INPUT and OUTPUT
- 0: 156.25MHz
- 0: 100MHz
- 1: 100MHz
- 1: 125MHz
- I2C ADDR = 0x6A
- Integrated output terminations providing Zo=100
- DEFAULT NO SPREAD
